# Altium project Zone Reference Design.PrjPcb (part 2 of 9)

## Sheet Input Supply.SchDoc
size 431 x 279 mm; Date: Not shown in title block; ApprovedBy: Not shown in title block; CheckedBy: Not shown in title block; Author: Not shown in title block; CompanyName: Not shown in title block; Engineer: Not shown in title block; Organization: Not shown in title block; Address1: Not shown in title block; Address2: Not shown in title block; Address3: Not shown in title block; Address4: Not shown in title block; DocumentNumber: 1; Revision: Use project parameter SCH_Rev; SheetNumber: 4; SheetTotal: 30; PageSetup: Record=PageOptions¦CenterHorizontal=True¦CenterVertical=True¦PrintScale=1.00¦XCorrection=1.00¦YCorrection=1.00¦PrintKind=0¦BorderSize=5000000¦LeftOffset=0¦BottomOffset=0¦Orientation=2¦PaperLength=1000¦PaperWidth=1000¦Scale=100¦PaperSource=15¦PrintQuality=600¦MediaType=1¦DitherType=10¦PaperKind=Letter¦PrintScaleMode=1
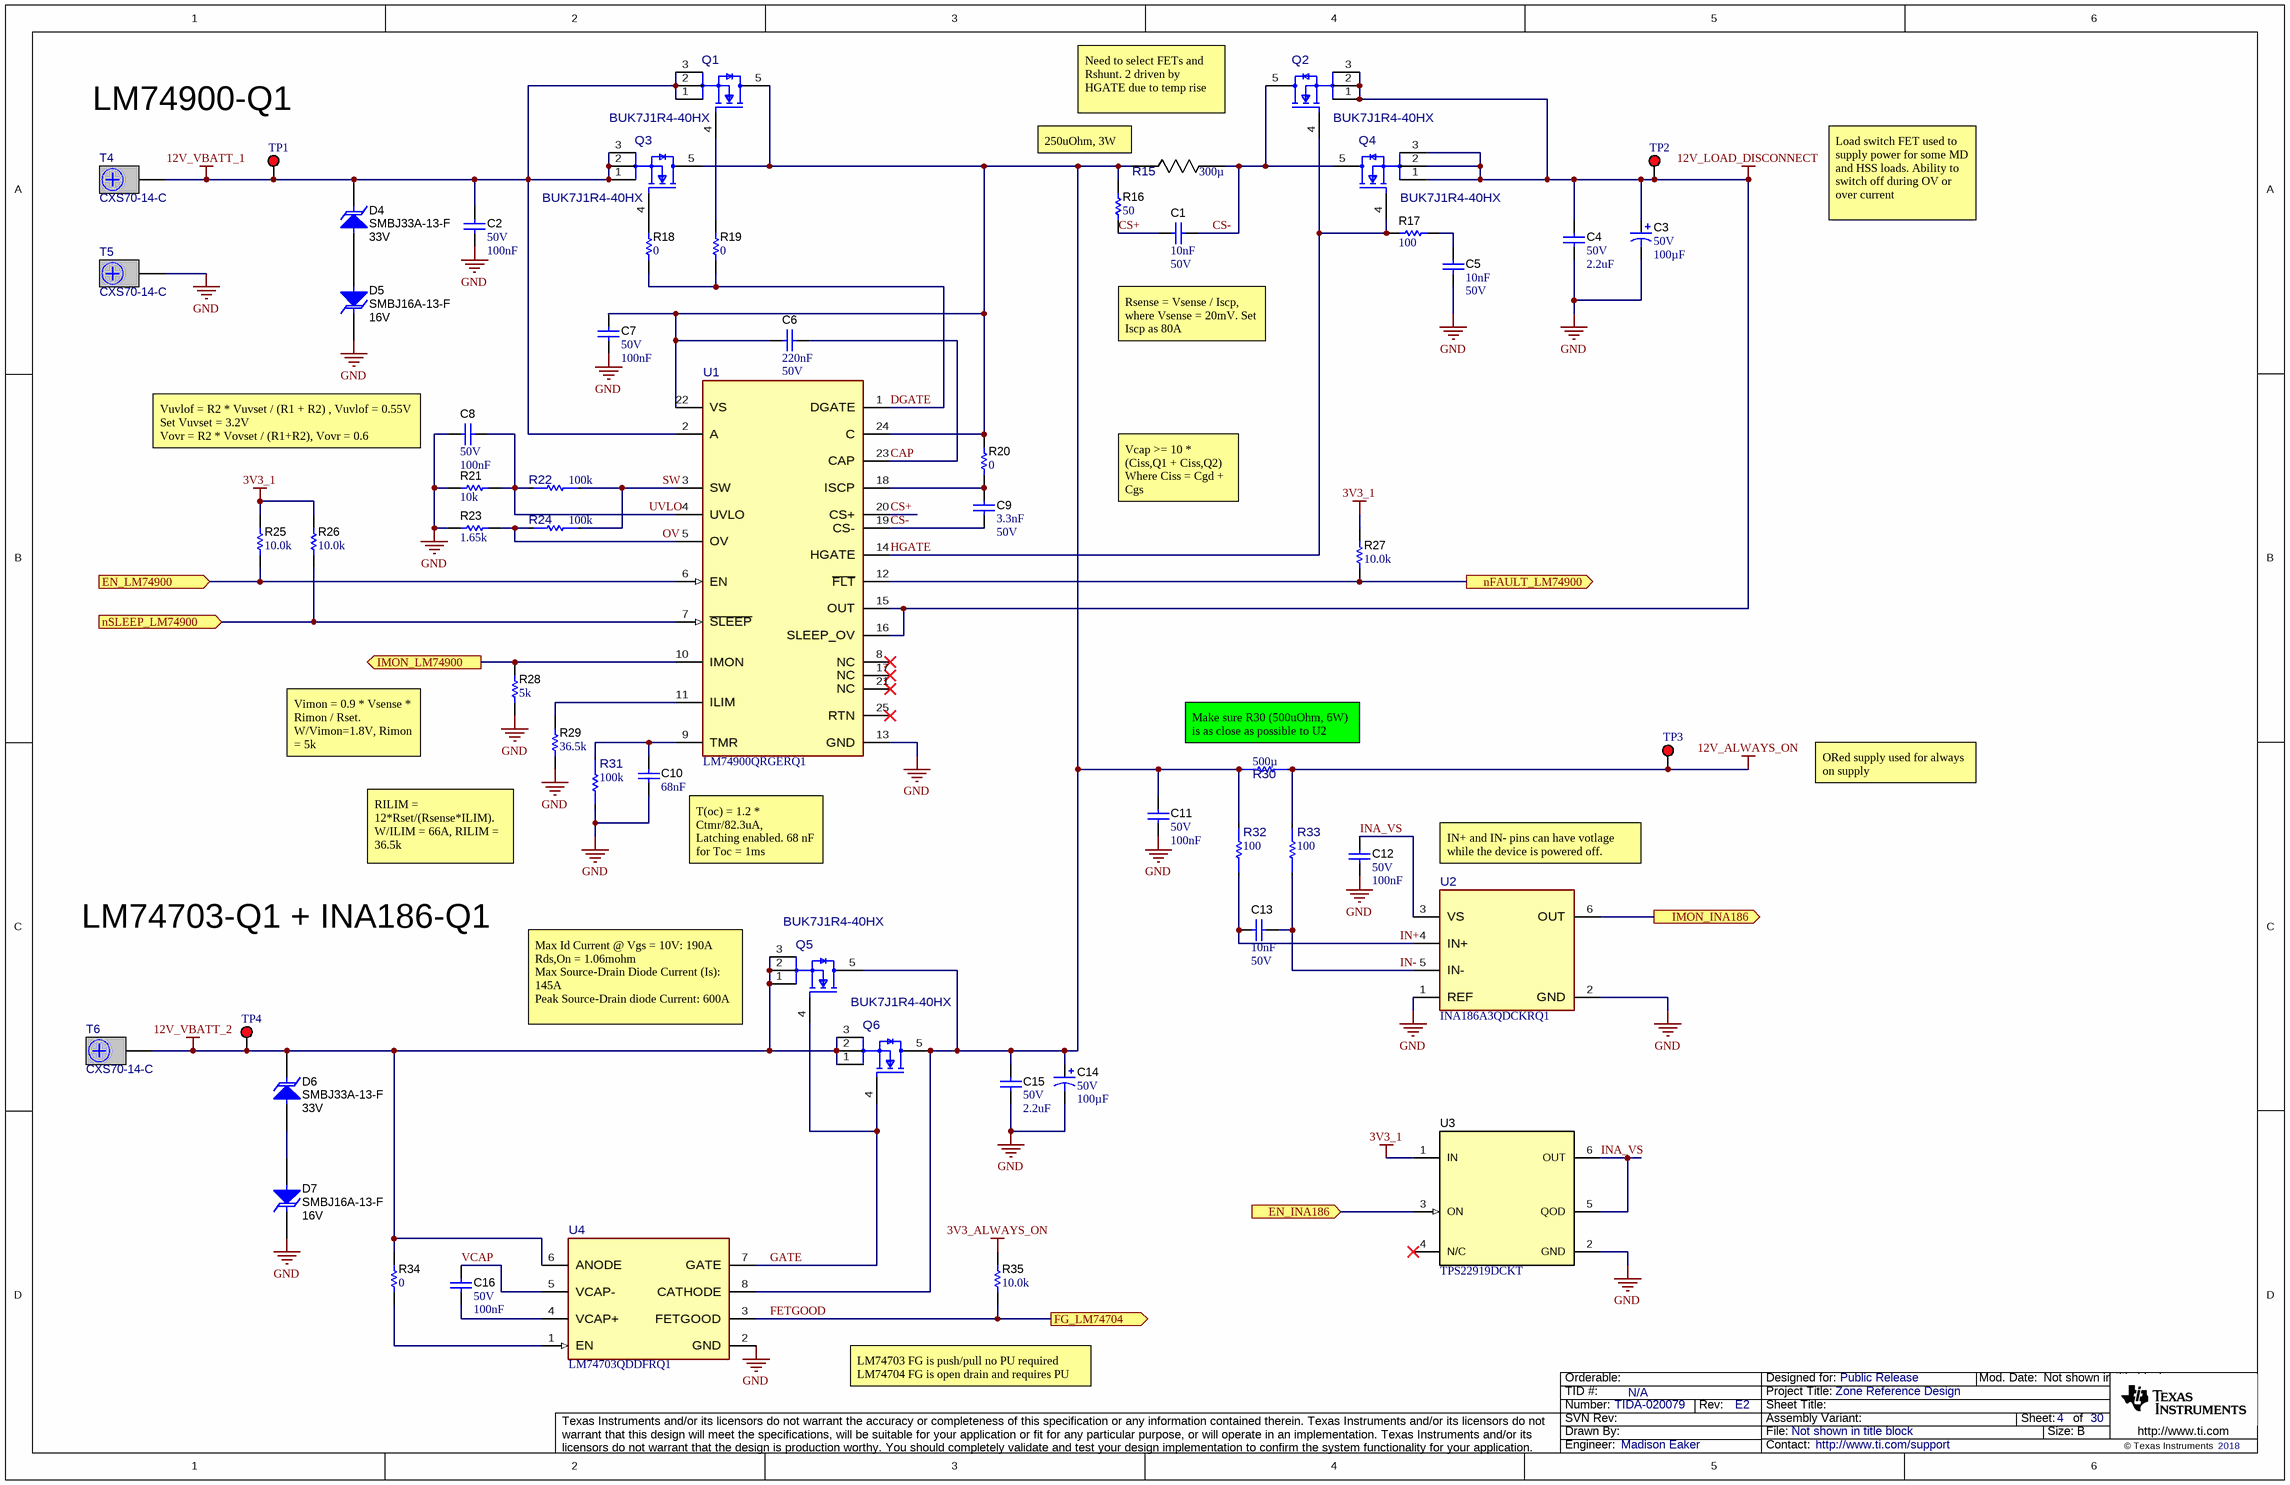
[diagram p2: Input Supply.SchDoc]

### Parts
C1  Cap_F: 10nF  VDC_V: 50V  [0603]  (hidden comment: C0603C103J5RACTU)
C2  VDC_V: 50V  Cap_F: 100nF  [0603L]  (hidden comment: 06035C104K4Z4A)
C3  VDC_V: 50V  ValueDisplayed: 100µF  [Panasonic_SMT_800x1020]  (hidden comment: EEEFP1H101AP)
C4  VDC_V: 50V  ValueDisplayed: 2.2uF  [0603]  (hidden comment: GRM188R61H225KE11D)
C5  Cap_F: 10nF  VDC_V: 50V  [0603]  (hidden comment: C0603C103J5RACTU)
C6  Cap_F: 220nF  VDC_V: 50V  [0603]  (hidden comment: GCM188R71H224KA64D)
C7  VDC_V: 50V  Cap_F: 100nF  [0603L]  (hidden comment: 06035C104K4Z4A)
C8  VDC_V: 50V  Cap_F: 100nF  [0603L]  (hidden comment: 06035C104K4Z4A)
C9  Cap_F: 3.3nF  VDC_V: 50V  [0603]  (hidden comment: C0603C332K5RACTU)
C10  Cap_F: 68nF  [0603]  (hidden comment: 06035C104KAZ2A)
C11  VDC_V: 50V  Cap_F: 100nF  [0603L]  (hidden comment: 06035C104K4Z4A)
C12  VDC_V: 50V  Cap_F: 100nF  [0603L]  (hidden comment: 06035C104K4Z4A)
C13  Cap_F: 10nF  VDC_V: 50V  [0603]  (hidden comment: C0603C103J5RACTU)
C14  VDC_V: 50V  ValueDisplayed: 100µF  [Panasonic_SMT_800x1020]  (hidden comment: EEEFP1H101AP)
C15  VDC_V: 50V  ValueDisplayed: 2.2uF  [0603]  (hidden comment: GRM188R61H225KE11D)
C16  VDC_V: 50V  Cap_F: 100nF  [0603L]  (hidden comment: 06035C104K4Z4A)
D4  SMBJ33A-13-F  value 33V  [SMB]
D5  SMBJ16A-13-F  value 16V  [SMB]
D6  SMBJ33A-13-F  value 33V  [SMB]
D7  SMBJ16A-13-F  value 16V  [SMB]
Q1  BUK7J1R4-40HX  [FP-BUK7J1R4-40HX_LFPAK56E-MFG]
Q2  BUK7J1R4-40HX  [FP-BUK7J1R4-40HX_LFPAK56E-MFG]
Q3  BUK7J1R4-40HX  [FP-BUK7J1R4-40HX_LFPAK56E-MFG]
Q4  BUK7J1R4-40HX  [FP-BUK7J1R4-40HX_LFPAK56E-MFG]
Q5  BUK7J1R4-40HX  [FP-BUK7J1R4-40HX_LFPAK56E-MFG]
Q6  BUK7J1R4-40HX  [FP-BUK7J1R4-40HX_LFPAK56E-MFG]
R15  Res_ohm: 300µ  [FP-PU2512FKGP60U3L_2512 (6432 Metric)-MFG]  (hidden comment: PU2512FKGP60U3L)
R16  ValueDisplayed: 50  [0603]  (hidden comment: CRCW060350R0FKEA)
R17  ValueDisplayed: 100  [0603]  (hidden comment: ERJ-3GEY0R00V)
R18  ValueDisplayed: 0  [0603]  (hidden comment: ERJ-3GEY0R00V)
R19  ValueDisplayed: 0  [0603]  (hidden comment: ERJ-3GEY0R00V)
R20  ValueDisplayed: 0  [0603]  (hidden comment: CRCW060350R0FKEA)
R21  ValueDisplayed: 10k  [0603]  (hidden comment: RT0603BRD0720K8L)
R22  value 100k  [FP-ERJ-PB3B1003V_0603-IPC_A]  (hidden comment: ERJ-PB3B1003V)
R23  ValueDisplayed: 1.65k  [0603]  (hidden comment: RT0603BRD071K62L)
R24  value 100k  [FP-ERJ-PB3B1003V_0603-IPC_A]  (hidden comment: ERJ-PB3B1003V)
R25  ValueDisplayed: 10.0k  [0603]  (hidden comment: ERJ-3EKF1002V)
R26  ValueDisplayed: 10.0k  [0603]  (hidden comment: ERJ-3EKF1002V)
R27  ValueDisplayed: 10.0k  [0603]  (hidden comment: ERJ-3EKF1002V)
R28  ValueDisplayed: 5k  [0603]  (hidden comment: RC0603FR-0730KL)
R29  ValueDisplayed: 36.5k  [0603]  (hidden comment: RC0603FR-0736K5L)
R30  value 500µ  [FP-CSS2H-2512R-L500F_2512-MFG]  (hidden comment: CSS2H-2512R-L500F)
R31  value 100k  [FP-ERJ-PB3B1003V_0603-IPC_A]  (hidden comment: ERJ-PB3B1003V)
R32  value 100  [FP-SG73S1JTTD101J_0603-MFG]  (hidden comment: SG73S1JTTD101J)
R33  value 100  [FP-SG73S1JTTD101J_0603-MFG]  (hidden comment: SG73S1JTTD101J)
R34  ValueDisplayed: 0  [0603]  (hidden comment: ERJ-3GEY0R00V)
R35  ValueDisplayed: 10.0k  [0603]  (hidden comment: ERJ-3EKF1002V)
T4  CXS70-14-C  [Panduit_CXS70-14-C]
T5  CXS70-14-C  [Panduit_CXS70-14-C]
T6  CXS70-14-C  [Panduit_CXS70-14-C]
TP1  5010  [Keystone5010]  (value not drawn)
TP2  5010  [Keystone5010]  (value not drawn)
TP3  5010  [Keystone5010]  (value not drawn)
TP4  5010  [Keystone5010]  (value not drawn)
U1  LM74900QRGERQ1  [RGE0024T-MFG]
U2  INA186A3QDCKRQ1  [DCK0006A-MFG]
U3  TPS22919DCKT  [DCK0006A_N]
U4  LM74703QDDFRQ1  [DDF0008A-MFG]

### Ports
EN_INA186 (in), EN_LM74900 (in), FG_LM74704 (out), IMON_INA186 (out), IMON_LM74900 (out), nFAULT_LM74900 (out), nSLEEP_LM74900 (in)

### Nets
3V3_1: R25.2 R26.2 R27.2 U3.1(IN)
3V3_ALWAYS_ON: R35.2
12V_ALWAYS_ON: R30.2 R33.2 TP3.1
12V_LOAD_DISCONNECT: C3.1(+) C4.1 Q2.1(S) Q2.2(S) Q2.3(S) Q4.1(S) Q4.2(S) Q4.3(S) TP2.1 U1.15(OUT) U1.16(SLEEP_OV)  [project net VS]
12V_VBATT_1: C2.1 D4.1(K) Q1.1(S) Q1.2(S) Q1.3(S) Q3.1(S) Q3.2(S) Q3.3(S) T4.1 TP1.1 U1.2(A)
12V_VBATT_2: D6.1(K) Q5.1(S) Q5.2(S) Q5.3(S) Q6.1(S) Q6.2(S) Q6.3(S) R34.2 T6.1 TP4.1 U4.6(ANODE)
GND: C2.2 C3.2(-) C4.2 C5.1 C7.2 C8.1 C10.2 C11.2 C12.2 C14.2(-) C15.2 D5.1(K) D7.1(K) R21.1 R23.1 R28.2 R29.1 R31.2 T5.1 U1.13(GND) U2.1(REF) U2.2(GND) U3.2(GND) U4.2(GND)
ADC0_AIN0: R28.1 U1.10(IMON) ; port IMON_LM74900
ADC0_AIN1: U2.6(OUT) ; port IMON_INA186
CAP: C6.1 U1.23(CAP)  [project net CAP_4]
CS+: C1.2 R16.1 U1.20(CS+)  [project net CS+_4]
CS-: C1.1 C9.2 Q2.5(D) Q4.5(D) R15.2 U1.19(CS-)  [project net CS-_4]
DGATE: R18.1 R19.1 U1.1(DGATE)  [project net DGATE_4]
EN_INA186: R25.1 U1.6(EN) U3.3(ON) ; port EN_INA186, port EN_LM74900
EPWM5_A: R27.1 U1.12(~{FLT}) ; port nFAULT_LM74900
EQEP0_A: R26.1 U1.7(~{SLEEP}) ; port nSLEEP_LM74900
FETGOOD: R35.1 U4.3(FETGOOD) ; port FG_LM74704
GATE: Q5.4(G) Q6.4(G) U4.7(GATE)  [project net GATE_4]
HGATE: Q2.4(G) Q4.4(G) R17.1 U1.14(HGATE)  [project net HGATE_4]
IN+: C13.2 R32.1 U2.4(IN+)  [project net IN+_4]
IN-: C13.1 R33.1 U2.5(IN-)  [project net IN-_4]
INA_VS: C12.1 U2.3(VS) U3.5(QOD) U3.6(OUT)  [project net INA_VS_4]
OV: R23.2 R24.2 U1.5(OV)  [project net OV_4]
SW: R22.1 R24.1 U1.3(SW)  [project net SW_4]
UVLO: C8.2 R21.2 R22.2 U1.4(UVLO)  [project net UVLO_4]
VCAP: C16.1 U4.5(VCAP-)  [project net VCAP_4]
NetC5_2: C5.2 R17.2
NetC6_2: C6.2 C7.1 C11.1 C14.1(+) C15.1 Q1.5(D) Q3.5(D) Q5.5(D) Q6.5(D) R15.1 R16.2 R20.2 R30.1 R32.2 U1.22(VS) U1.24(C) U4.8(CATHODE)
NetC9_1: C9.1 R20.1 U1.18(ISCP)
NetC10_1: C10.1 R31.1 U1.9(TMR)
NetC16_2: C16.2 U4.4(VCAP+)
NetD4_2: D4.2(A) D5.2(A)
NetD6_2: D6.2(A) D7.2(A)
NetQ1_4: Q1.4(G) R19.2
NetQ3_4: Q3.4(G) R18.2
NetR29_2: R29.2 U1.11(ILIM)
NetR34_1: R34.1 U4.1(EN)

Not connected (* = marked no-connect by the designer): U1 8(NC)* 17(NC)* 21(NC)* 25(RTN)*; U3 4(N/C)*

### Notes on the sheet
- LM74900-Q1
- 250uOhm, 3W
- Need to select FETs and Rshunt. 2 driven by HGATE due to temp rise
- Load switch FET used to supply power for some MD and HSS loads. Ability to switch off during OV or over current
- Rsense = Vsense / Iscp, where Vsense = 20mV. Set Iscp as 80A
- Vuvlof = R2 * Vuvset / (R1 + R2) , Vuvlof = 0.55V
  Set Vuvset = 3.2V
  Vovr = R2 * Vovset / (R1+R2), Vovr = 0.6
- Vcap >= 10 * (Ciss,Q1 + Ciss,Q2)
  Where Ciss = Cgd + Cgs
- Vimon = 0.9 * Vsense * Rimon / Rset. W/Vimon=1.8V, Rimon = 5k
- (near R30) Make sure R30 (500uOhm, 6W) is as close as possible to U2
- ORed supply used for always on supply
- RILIM = 12*Rset/(Rsense*ILIM). W/ILIM = 66A, RILIM = 36.5k
- T(oc) = 1.2 * Ctmr/82.3uA,
  Latching enabled. 68 nF for Toc = 1ms
- IN+ and IN- pins can have votlage while the device is powered off.
- LM74703-Q1 + INA186-Q1
- Max Id Current @ Vgs = 10V: 190A
  Rds,On = 1.06mohm
  Max Source-Drain Diode Current (Is): 145A
  Peak Source-Drain diode Current: 600A
- LM74703 FG is push/pull no PU required
  LM74704 FG is open drain and requires PU

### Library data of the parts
C1 C5 C13 = CMP-0006850-4: CAP, CERM, 0.01 uF, 50 V, +/- 5%, X7R, 0603; Manufacturer: Kemet; TaMin_C: -55°C; Polarized: N; SizeAreaWB_mm2: 4.68; Value1: Unknown; U/M: EA; Value: 0.01uF; TaMax_C: 125°C; SizeZ_mm: 1; SizeX_mm: 1.6; SizeY_mm: 0.8; SizeArea_mm2: 1.28; AEC Category: Q200
C2 C7 C8 C11 C12 C16 = CMP-0084736-1: CAP, CERM, 0.1 µF, 50 V,+/- 10%, X7R, AEC-Q200 Grade 0, 0603; Manufacturer: AVX; SizeX_mm: 1.6; AEC Qualified: Y; Value: 0.1uF; TaMin_C: -55°C; TaMax_C: 125°C; SizeY_mm: 0.8; SizeAreaWB_mm2: 4.68; AEC Grade: 0; SizeArea_mm2: 1.28; SizeZ_mm: 1; ValueDisplayed: 0.1µF; U/M: EA; Cap_Case: 0603; Polarized: N; AEC Category: Q200
C3 C14 = CMP-0077295-1: CAP, AL, 100 µF, 50 V, +/- 20%, 0.18 ohm, AEC-Q200 Grade 2, SMD; Manufacturer: Panasonic; IRMS_A: 670mA; SizeAreaWB_mm2: 106.09; SizeArea_mm2: 68.89; AEC Qualified: Y; AEC Category: Q200; Value: 100uF; TaMax_C: 105°C; SizeZ_mm: 10.5; AEC Grade: 2; TaMin_C: -55°C; SizeY_mm: 8.3; U/M: EA; CompType: Capacitor; ESR_ohm: 0.18; Cap_Case: 8x10.2mm
C4 C15 = CMP-0007353-5: CAP, CERM, 2.2 uF, 50 V, +/- 10%, X5R, 0603; Manufacturer: MuRata; TaMin_C: -55°C; Polarized: N; SizeAreaWB_mm2: 4.68; Value1: Unknown; U/M: EA; Value: 2.2uF; TaMax_C: 85°C; SizeZ_mm: 1; SizeX_mm: 1.6; SizeY_mm: 0.8; SizeArea_mm2: 1.28; Cap_F: 2.2µF; AEC Category: Q200
C6 = CMP-0007145-4: CAP, CERM, 0.22 uF, 50 V, +/- 10%, X7R, AEC-Q200 Grade 1, 0603; Manufacturer: MuRata; TaMin_C: -55°C; Polarized: N; SizeAreaWB_mm2: 4.68; Value1: Unknown; U/M: EA; Value: 0.22uF; TaMax_C: 125°C; SizeZ_mm: 1; SizeX_mm: 1.6; SizeY_mm: 0.8; SizeArea_mm2: 1.28; AEC Qualified: Y; AEC Category: Q200
C9 = CMP-0006922-4: CAP, CERM, 3300 pF, 50 V, +/- 10%, X7R, 0603; Manufacturer: Kemet; TaMin_C: -55°C; Polarized: N; SizeAreaWB_mm2: 4.68; Value1: Unknown; U/M: EA; Value: 3300pF; TaMax_C: 125°C; SizeZ_mm: 1; SizeX_mm: 1.6; SizeY_mm: 0.8; SizeArea_mm2: 1.28; AEC Category: Q200
C10 = CMP-0079095-1: CAP, CERM, 0.1 µF, 50 V,+/- 10%, X7R, AEC-Q200 Grade 1, 0603; Manufacturer: AVX; SizeAreaWB_mm2: 4.68; SizeArea_mm2: 1.28; AEC Qualified: Y; AEC Category: Q200; Value: 0.1uF; TaMax_C: 125°C; SizeZ_mm: 1; Polarized: N; TaMin_C: -55°C; VDC_V: 50V; SizeY_mm: 0.8; U/M: EA; SizeX_mm: 1.6; ValueDisplayed: 0.1µF
D4 D6 = CMP-0005563-4: Diode, TVS, Uni, 33 V, 53.3 Vc, SMB; Manufacturer: Diodes Inc.; Vc: 53.3V; Value1: 600W; Vbr_Max: 42.2V; Vbr_Min: 36.7V; SizeX_mm: 5.6; SizeAreaWB_mm2: 44.156; AEC Category: Q101; SizeY_mm: 3.81; SizeZ_mm: 2.6; Ipp: 11.3A; SizeArea_mm2: 21.336
D5 D7 = CMP-0005547-4: Diode, TVS, Uni, 16 V, 26 Vc, SMB; Manufacturer: Diodes Inc.; SizeArea_mm2: 21.336; SizeY_mm: 3.81; Vbr_Min: 17.8V; Ppk: 600W; AEC Category: Q101; SizeZ_mm: 2.6; Ipp: 23.1A; SizeAreaWB_mm2: 44.156; Vc: 26V; Vbr_Max: 20.5V; SizeX_mm: 5.6
Q1-Q6 = CMP-0098150-1: Trans MOSFET N-CH 40V 190A Automotive 5-Pin(4+Tab) LFPAK T/R; Manufacturer: Nexperia; Drain To Source Breakdown Voltage: 42V; Threshold Vgs Max: 3.6V; Turn On Delay Time: 19ns; ChMode: False; Standoff Height: 0mm; Rdson45_ohm: 1.06m; Power_W: 395W; TJmax_C: +175°C; Pulse Drain Current: 600A; QgTyp_nC: 73nC @ 10V; Vgs_V: 20V; AEC Grade: Grade 0; AEC Qualified: Yes; Turn Off Delay Time: 43ns; VdsMax_V: 1.2V; Input Capacitace At Vds: 5436pF @ 25V; Number Of Channels: 1; SizeZ_mm: 1.25mm; Reverse Recovery Charge: 39nC; Reverse Recovery Time: 37ns; Typ Forward Diode Voltage: 0.8V; Threshold Vgs Min: 2.4V
R15 = CMP-0086899-1: 300 µOhms ±1% 6W Chip Resistor 2512 (6432 Metric) Automotive AEC-Q200, Current Sense, Moisture Resistant Metal Element; Manufacturer: Yageo; SizeZ_mm: 1.08mm; TempCo: 200ppm/°C; AEC Qualified: Yes; Symbol Name: SYM-PU2512FKGP60U3L; AEC Grade: Grade 0
R16 = CMP-0022479-4: RES, 50, 1%, 0.1 W, AEC-Q200 Grade 0, 0603; Manufacturer: Vishay-Dale; Power_W: 100mW; TempCo: 100 ppm/C; Value_Code: 50R0; Value: 50; SizeX_mm: 1.6; SizeY_mm: 0.8; SizeZ_mm: 1; Value2: 0.1W; SizeArea_mm2: 1.28; AEC Qualified: Y; VDC_V: 75V; AEC Category: Q200; AEC Grade: 0
R17-R19 R34 = CMP-0025874-4: RES, 0, 5%, 0.1 W, AEC-Q200 Grade 0, 0603; Manufacturer: Panasonic; Power_W: 100mW; TempCo: 600 ppm/C; Value_Code: 0000; Value: 0; EIA_Code: E24; SizeX_mm: 1.6; SizeY_mm: 0.8; SizeZ_mm: 1; Value2: 0.1W; SizeArea_mm2: 1.28; AEC Qualified: Y; VDC_V: 50V; AEC Category: Q200; SizeAreaWB_mm2: 4.68
R20 = CMP-0022479-4: RES, 50, 1%, 0.1 W, AEC-Q200 Grade 0, 0603; Manufacturer: Vishay-Dale; Power_W: 100mW; TempCo: 100 ppm/C; Value_Code: 50R0; Value: 50; SizeX_mm: 1.6; SizeY_mm: 0.8; SizeZ_mm: 1; Value2: 0.1W; SizeArea_mm2: 1.28; AEC Qualified: Y; VDC_V: 75V; AEC Category: Q200
R21 = CMP-0023930-3: RES, 20.8 k, 0.1%, 0.1 W, 0603; Manufacturer: Yageo America; Power_W: 100mW; TempCo: 25 ppm/C; Value_Code: 20k8; U/M: EA; Value: 20.8k; EIA_Code: E192; SizeX_mm: 1.6; SizeY_mm: 0.8; SizeZ_mm: 1; Value2: 0.1W; SizeArea_mm2: 1.28; VDC_V: 75V; AEC Category: Q200
R22 R24 R31 = CMP-0092407-1: Res Thick Film 0603 100K Ohm 0.1% 0.2W(1/5W) ±50ppm/°C Pad SMD Automotive T/R; Manufacturer: Panasonic; Power_W: 200mW; VDC_V: 150V; AEC Qualified: Yes; SizeZ_mm: 0.55mm; AEC Grade: Grade 0
R23 = CMP-0023900-3: RES, 1.62 k, 0.1%, 0.1 W, 0603; Manufacturer: Yageo America; Power_W: 100mW; TempCo: 25 ppm/C; Value_Code: 1k62; U/M: EA; Value: 1.62k; EIA_Code: E192; SizeX_mm: 1.6; SizeY_mm: 0.8; SizeZ_mm: 1; Value2: 0.1W; SizeArea_mm2: 1.28; VDC_V: 75V; AEC Category: Q200
R25-R27 R35 = CMP-0022684-3: RES, 10.0 k, 1%, 0.1 W, 0603; Manufacturer: Panasonic; Power_W: 100mW; TempCo: 100 ppm/C; Value_Code: 10k0; U/M: EA; Value: 10.0k; EIA_Code: E96; Res_ohm: 10k; SizeX_mm: 1.6; SizeY_mm: 0.8; SizeZ_mm: 1; Value2: 0.1W; SizeArea_mm2: 1.28; VDC_V: 75V; AEC Category: Q200
R28 = CMP-0023020-5: RES, 30.0 k, 1%, 0.1 W, 0603; Manufacturer: Yageo; Power_W: 100mW; TempCo: 100 ppm/C; Value_Code: 30k0; Value: 30.0k; Res_ohm: 30k; SizeX_mm: 1.6; SizeY_mm: 0.8; SizeZ_mm: 1; Value2: 0.1W; SizeArea_mm2: 1.28; AEC Qualified: N; VDC_V: 75V; AEC Category: Q200; SizeAreaWB_mm2: 4.68
R29 = CMP-0023056-5: RES, 36.5 k, 1%, 0.1 W, 0603; Manufacturer: Yageo; Power_W: 100mW; TempCo: 100 ppm/C; Value_Code: 36k5; Value: 36.5k; EIA_Code: E96; SizeX_mm: 1.6; SizeY_mm: 0.8; SizeZ_mm: 1; Value2: 0.1W; SizeArea_mm2: 1.28; AEC Qualified: N; VDC_V: 75V; AEC Category: Q200; SizeAreaWB_mm2: 4.68
R30 = CMP-0095938-1: 500 µOhms ±1% 6W Chip Resistor 2512 (6432 Metric) Automotive AEC-Q200, Current Sense Metal Element; Manufacturer: Bourns; AEC Qualified: Yes; Standoff Height: 0.15mm; SizeZ_mm: 1.23mm; TempCo: 100ppm/°C; AEC Grade: Grade 0
R32 R33 = CMP-0095262-1: 100 Ohms ±5% 0.2W, 1/5W Chip Resistor 0603 (1608 Metric) Automotive AEC-Q200, Moisture Resistant, Pulse Withstanding Thick Film; Manufacturer: KOA Speer; AEC Qualified: Yes; AEC Grade: Grade 0; VDC_V: 150V; TaMax_C: +70°C; TempCo: 100ppm/°C; Power_W: 200mW; SizeZ_mm: 0.55mm
T4-T6 = CMP-0075010-2: Terminal 70A Lug; Manufacturer: Panduit; CompType: Screw Terminal; CT: False; Green_Lifecycle: Not Set; Green_REACh: Incomplete
TP1-TP4 = CMP-0055147-2: Test Point, Multipurpose, Red, TH; Manufacturer: Keystone Electronics; CT: TRUE; ContactFinish: Silver; Green_Lifecycle: Active; CNHeader: FALSE; Green_REACh: Passed
U1 = CMP-0122616-1: Automotive ideal diode with circuit breaker, under- and overvoltage protection with fault output 24-VQFN -40 to 125; Manufacturer: Texas Instruments; SizeZ_mm: 1mm; AEC Qualified: Yes; AEC Grade: Grade 1; Max Supply Voltage: 65V; Min Supply Voltage: 3V; Nominal Supply Current: 630-635uA; Number Of Outputs: 1; Standoff Height: 0mm; TaMax_C: +125°C; TaMin_C: -40°C; TJmax_C: +150°C
U2 = CMP-0121214-1: SP Amp Current Sense Amp Single R-R O/P 5.5V Automotive AEC-Q100 6-Pin SC-70 T/R; Manufacturer: Texas Instruments; SizeZ_mm: 1.1mm; AEC Qualified: Yes; AEC Grade: Grade 1; Bandwidth: 35kHz; Input Bias Current: 0.0005uA; Input Offset Voltage: -0.003mV; Min Supply Voltage: 1.7V; Nominal Supply Current: 48uA; Number Of Channels: 1; Response Time: 30us; Standoff Height: 0mm; TaMax_C: +125°C; TaMin_C: -40°C; TJmax_C: +150°C; Voltage Gain: 0.1V/mV
U3 = CMP-0081107-1: 5.5-V, 1.5-A, 100-mohm Load Switch with Output Discharge, DCK0006A (SOT-SC70-6); Alternate PartNumber: TPS22919DCKR; Alternate Manufacturer: Texas Instruments; SizeAreaWB_mm2: 9.3; SizeZ_mm: 1.1; SizeX_mm: 2.1; SizeY_mm: 2; SizeArea_mm2: 4.2; CompType: IC; AEC Qualified: N; AEC Category: Q200
U4 = CMP-0122213-1: Automotive Ideal Diode Controller With External FET Health Indication; Manufacturer: Texas Instruments; SizeZ_mm: 1.1mm; AEC Qualified: Yes; AEC Grade: Grade 1; Max Supply Voltage: 65V; Min Supply Voltage: 3.2V; Nominal Supply Current: 80uA; Number Of Outputs: 1; Standoff Height: 0mm; TaMax_C: +125°C; TaMin_C: -40°C; TJmax_C: +150°C

## Sheet PMIC.SchDoc
size 431 x 279 mm; Date: Not shown in title block; ApprovedBy: Not shown in title block; CheckedBy: Not shown in title block; Author: Not shown in title block; CompanyName: Not shown in title block; Engineer: Not shown in title block; Organization: Not shown in title block; Address1: Not shown in title block; Address2: Not shown in title block; Address3: Not shown in title block; Address4: Not shown in title block; DocumentNumber: 1; Revision: Use project parameter SCH_Rev; SheetNumber: 3; SheetTotal: 30; PageSetup: Record=PageOptions¦CenterHorizontal=True¦CenterVertical=True¦PrintScale=1.00¦XCorrection=1.00¦YCorrection=1.00¦PrintKind=0¦BorderSize=5000000¦LeftOffset=0¦BottomOffset=0¦Orientation=2¦PaperLength=1000¦PaperWidth=1000¦Scale=100¦PaperSource=15¦PrintQuality=600¦MediaType=1¦DitherType=10¦PaperKind=Letter¦PrintScaleMode=1
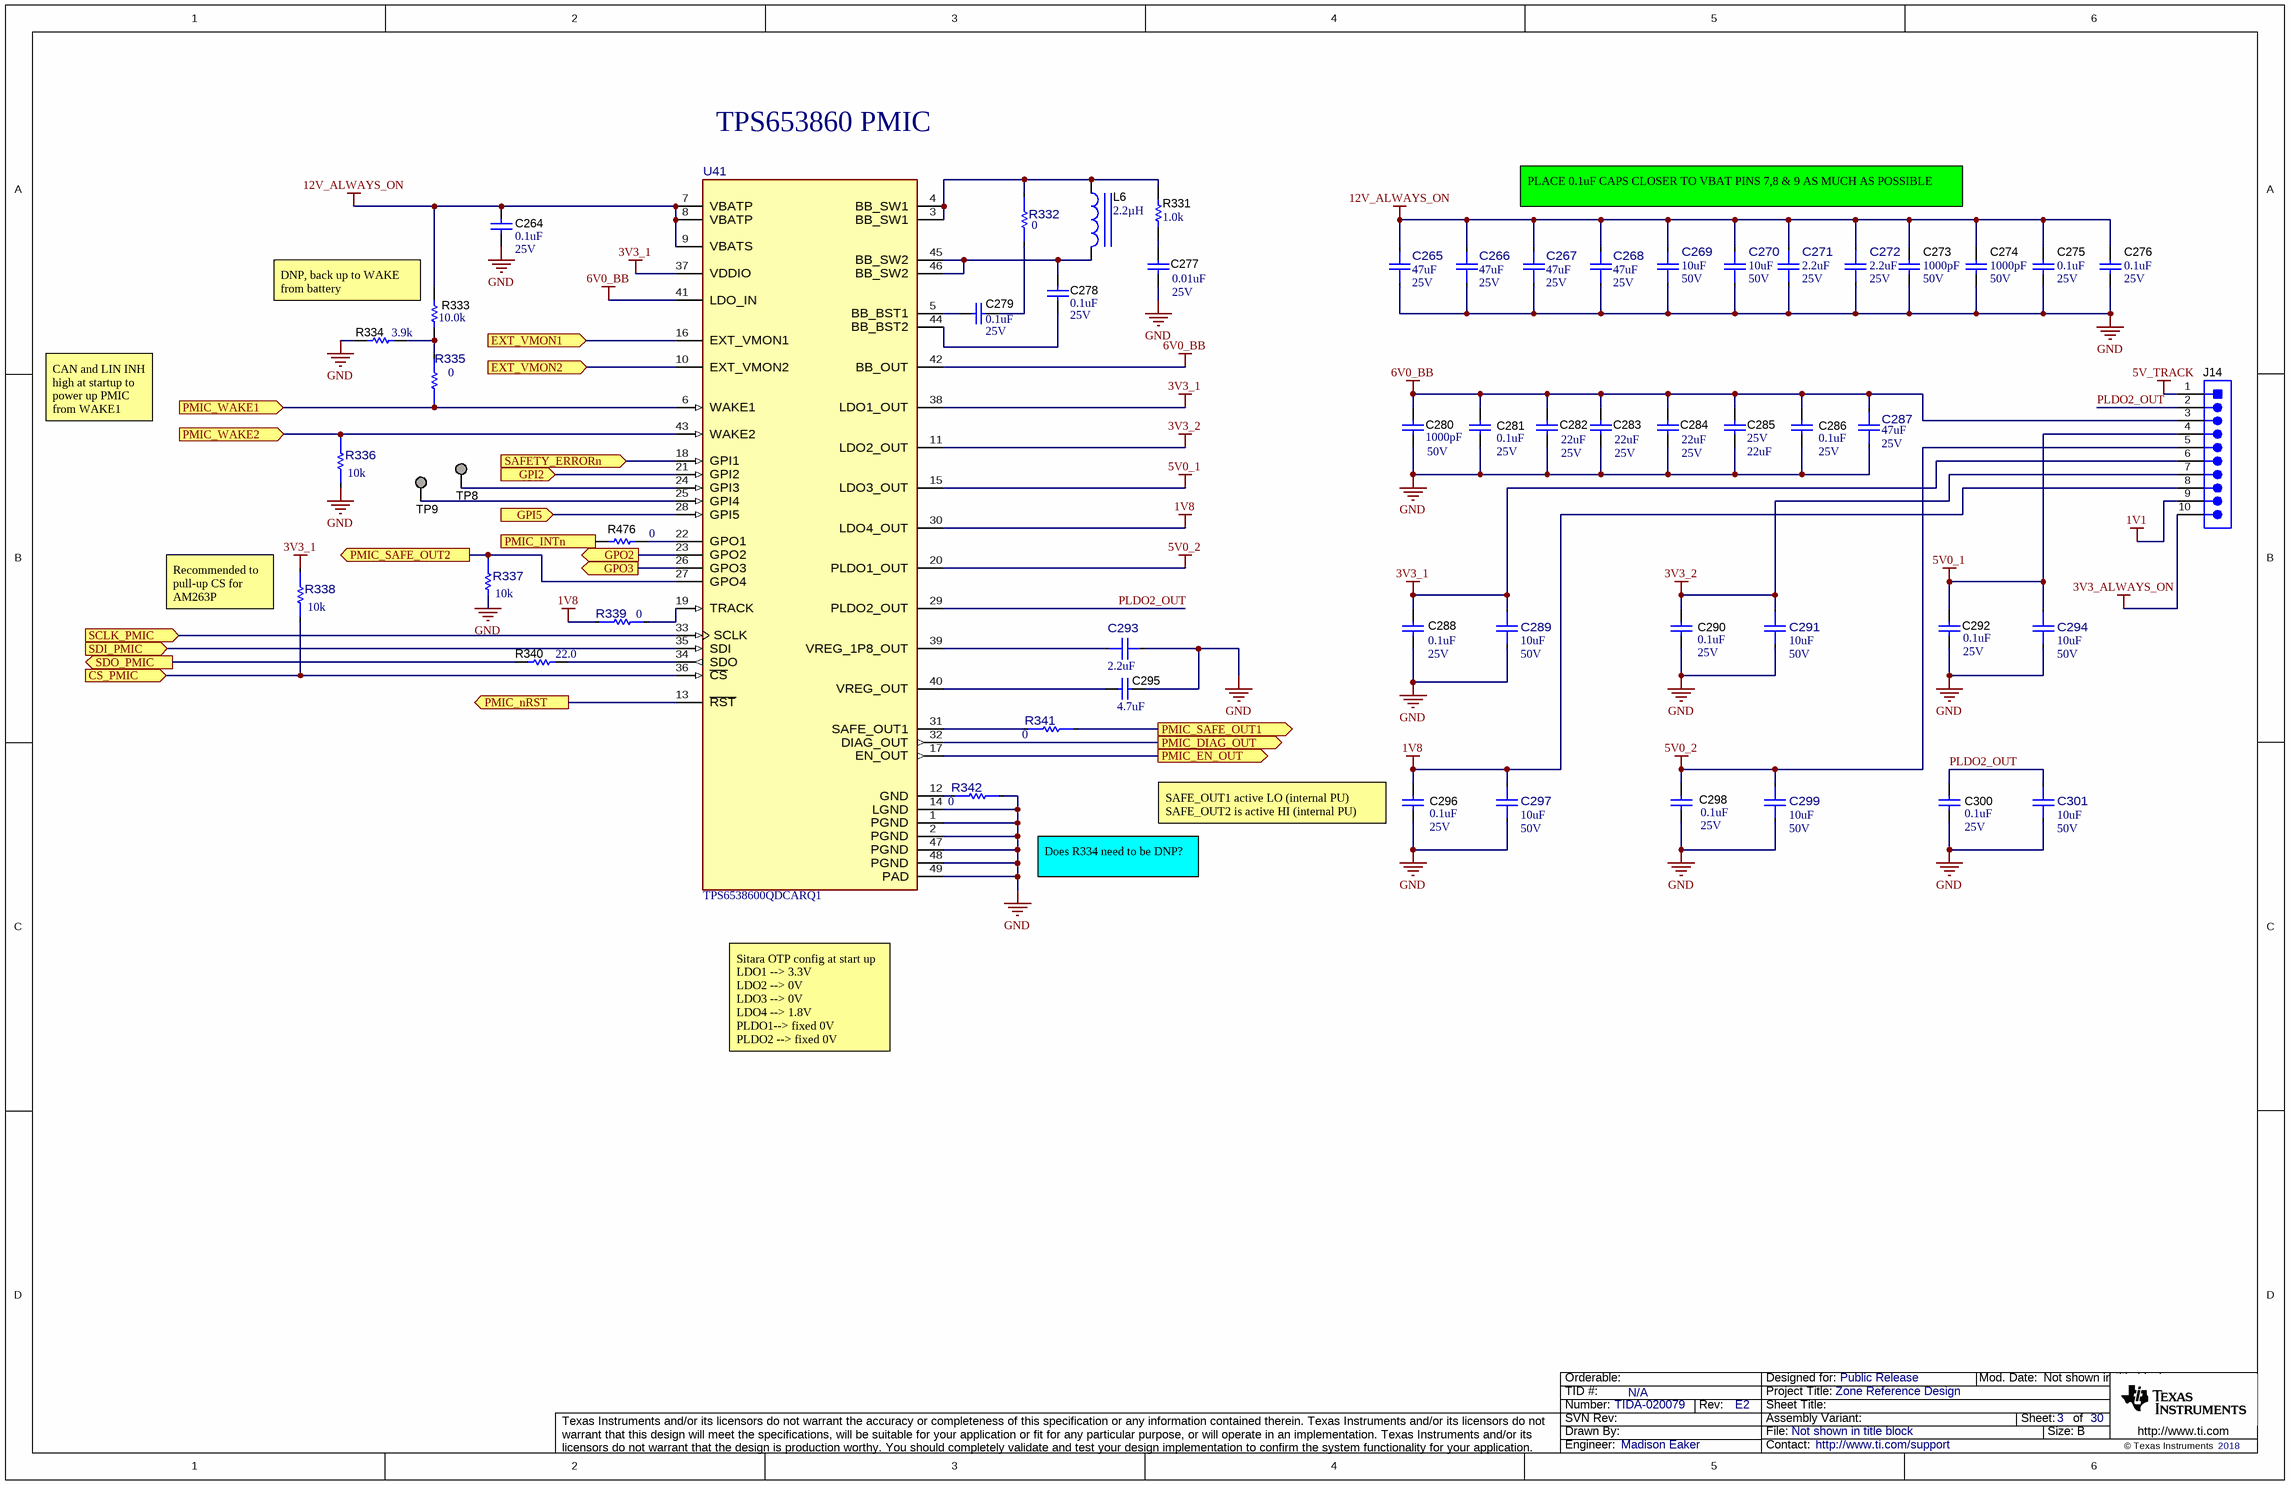
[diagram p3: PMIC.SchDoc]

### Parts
C264  VDC_V: 25V  ValueDisplayed: 0.1uF  [0402]  (hidden comment: GRM155R71E104KE14D)
C265  ValueDisplayed: 47uF  VDC_V: 25V  [FP-GMC31X5R476M25NT_1206-MFG]  (hidden comment: GMC31X5R476M25NT)
C266  ValueDisplayed: 47uF  VDC_V: 25V  [FP-GMC31X5R476M25NT_1206-MFG]  (hidden comment: GMC31X5R476M25NT)
C267  ValueDisplayed: 47uF  VDC_V: 25V  [FP-GMC31X5R476M25NT_1206-MFG]  (hidden comment: GMC31X5R476M25NT)
C268  ValueDisplayed: 47uF  VDC_V: 25V  [FP-GMC31X5R476M25NT_1206-MFG]  (hidden comment: GMC31X5R476M25NT)
C269  ValueDisplayed: 10uF  VDC_V: 50V  [FP-GRM21BR61H106KE43L_0805-MFG]  (hidden comment: GRM21BR61H106KE43L)
C270  ValueDisplayed: 10uF  VDC_V: 50V  [FP-GRM21BR61H106KE43L_0805-MFG]  (hidden comment: GRM21BR61H106KE43L)
C271  ValueDisplayed: 2.2uF  VDC_V: 25V  [FP-GRM155R61E225KE11D_0402 (1005 metric)-MFG]  (hidden comment: GRM155R61E225KE11D)
C272  ValueDisplayed: 2.2uF  VDC_V: 25V  [FP-GRM155R61E225KE11D_0402 (1005 metric)-MFG]  (hidden comment: GRM155R61E225KE11D)
C273  Value2: 50V  ValueDisplayed: 1000pF  [0402]  (hidden comment: GRM1555C1H102JA01D)
C274  Value2: 50V  ValueDisplayed: 1000pF  [0402]  (hidden comment: GRM1555C1H102JA01D)
C275  Value2: 25V  ValueDisplayed: 0.1uF  [0402]  (hidden comment: GRM155R71E104KE14D)
C276  Value2: 25V  ValueDisplayed: 0.1uF  [0402]  (hidden comment: GRM155R71E104KE14D)
C277  Value2: 25V  ValueDisplayed: 0.01uF  [0402]  (hidden comment: GCM155R71E103KA37D)
C278  VDC_V: 25V  ValueDisplayed: 0.1uF  [0402]  (hidden comment: GRM155R71E104KE14D)
C279  VDC_V: 25V  ValueDisplayed: 0.1uF  [0402]  (hidden comment: GRM155R71E104KE14D)
C280  VDC_V: 50V  ValueDisplayed: 1000pF  [0402]  (hidden comment: GRM1555C1H102JA01D)
C281  VDC_V: 25V  ValueDisplayed: 0.1uF  [0402]  (hidden comment: GRM155R71E104KE14D)
C282  VDC_V: 25V  ValueDisplayed: 22uF  [0805_HV]  (hidden comment: GRM21BR61E226ME44L)
C283  VDC_V: 25V  ValueDisplayed: 22uF  [0805_HV]  (hidden comment: GRM21BR61E226ME44L)
C284  VDC_V: 25V  ValueDisplayed: 22uF  [0805_HV]  (hidden comment: GRM21BR61E226ME44L)
C285  VDC_V: 25V  ValueDisplayed: 22uF  [0805_HV]  (hidden comment: GRM21BR61E226ME44L)
C286  VDC_V: 25V  ValueDisplayed: 0.1uF  [0402]  (hidden comment: GRM155R71E104KE14D)
C287  ValueDisplayed: 47uF  VDC_V: 25V  [FP-GMC31X5R476M25NT_1206-MFG]  (hidden comment: GMC31X5R476M25NT)
C288  VDC_V: 25V  ValueDisplayed: 0.1uF  [0402]  (hidden comment: GRM155R71E104KE14D)
C289  ValueDisplayed: 10uF  VDC_V: 50V  [FP-GRM21BR61H106KE43L_0805-MFG]  (hidden comment: GRM21BR61H106KE43L)
C290  VDC_V: 25V  ValueDisplayed: 0.1uF  [0402]  (hidden comment: GRM155R71E104KE14D)
C291  ValueDisplayed: 10uF  VDC_V: 50V  [FP-GRM21BR61H106KE43L_0805-MFG]  (hidden comment: GRM21BR61H106KE43L)
C292  VDC_V: 25V  ValueDisplayed: 0.1uF  [0402]  (hidden comment: GRM155R71E104KE14D)
C293  ValueDisplayed: 2.2uF  [FP-GRM155R61E225KE11D_0402 (1005 metric)-MFG]  (hidden comment: GRM155R61E225KE11D)
C294  ValueDisplayed: 10uF  VDC_V: 50V  [FP-GRM21BR61H106KE43L_0805-MFG]  (hidden comment: GRM21BR61H106KE43L)
C295  ValueDisplayed: 4.7uF  [0402]  (hidden comment: GRM155R61A475MEAAD)
C296  VDC_V: 25V  ValueDisplayed: 0.1uF  [0402]  (hidden comment: GRM155R71E104KE14D)
C297  ValueDisplayed: 10uF  VDC_V: 50V  [FP-GRM21BR61H106KE43L_0805-MFG]  (hidden comment: GRM21BR61H106KE43L)
C298  VDC_V: 25V  ValueDisplayed: 0.1uF  [0402]  (hidden comment: GRM155R71E104KE14D)
C299  ValueDisplayed: 10uF  VDC_V: 50V  [FP-GRM21BR61H106KE43L_0805-MFG]  (hidden comment: GRM21BR61H106KE43L)
C300  VDC_V: 25V  ValueDisplayed: 0.1uF  [0402]  (hidden comment: GRM155R71E104KE14D)
C301  ValueDisplayed: 10uF  VDC_V: 50V  [FP-GRM21BR61H106KE43L_0805-MFG]  (hidden comment: GRM21BR61H106KE43L)
J14  TSW-110-07-G-S  [TSW-110-07-G-S]  (value not drawn)
L6  ValueDisplayed: 2.2µH  [CLF7045NI-D]  (hidden comment: CLF7045NIT-2R2N-D)
R331  ValueDisplayed: 1.0k  [0402]  (hidden comment: ERJ-2GEJ102X)
R332  value 0  [FP-ERJ-2GE0R00X_0402-MFG]  (hidden comment: ERJ-2GE0R00X)
R333  ValueDisplayed: 10.0k  [0402]  (hidden comment: AC0402FR-0710KL)
R334  ValueDisplayed: 3.9k  [0402]  (hidden comment: CRCW04023K90JNED)
R335  value 0  [FP-ERJ-2GE0R00X_0402-MFG]  (hidden comment: ERJ-2GE0R00X)
R336  value 10k  [FP-RC0402JR-0710KL_0402-MFG]  (hidden comment: RC0402JR-0710KL)
R337  value 10k  [FP-RC0402JR-0710KL_0402-MFG]  (hidden comment: RC0402JR-0710KL)
R338  value 10k  [FP-RC0402JR-0710KL_0402-MFG]  (hidden comment: RC0402JR-0710KL)
R339  value 0  [FP-ERJ-2GE0R00X_0402-MFG]  (hidden comment: ERJ-2GE0R00X)
R340  ValueDisplayed: 22.0  [0201]  (hidden comment: RC0201FR-0722RL)
R341  value 0  [FP-ERJ-2GE0R00X_0402-MFG]  (hidden comment: ERJ-2GE0R00X)
R342  value 0  [FP-ERJ-2GE0R00X_0402-MFG]  (hidden comment: ERJ-2GE0R00X)
R476  ValueDisplayed: 0  [0603]  (hidden comment: CRCW06030000Z0EA)
TP8  TESTPOINT  [TP_25MIL-SMT]  (value not drawn)  (no BOM)
TP9  TESTPOINT  [TP_25MIL-SMT]  (value not drawn)  (no BOM)
U41  TPS6538600QDCARQ1  [DCA0048J-MFG]

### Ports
CS_PMIC (in), EXT_VMON1 (in), EXT_VMON2 (in), GPI2 (in), GPI5 (in), GPO2 (out), GPO3 (out), PMIC_DIAG_OUT (out), PMIC_EN_OUT (out), PMIC_INTn (out), PMIC_nRST (out), PMIC_SAFE_OUT1 (out), PMIC_SAFE_OUT2 (out), PMIC_WAKE1 (in), PMIC_WAKE2 (in), SAFETY_ERRORn (in), SCLK_PMIC (in), SDI_PMIC (in), SDO_PMIC (out)

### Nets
1V1: J14.9
1V8: C296.1 C297.1 J14.8 R339.1 U41.30(LDO4_OUT)
3V3_1: C288.1 C289.1 J14.6 R338.1 U41.37(VDDIO) U41.38(LDO1_OUT)
3V3_2: C290.1 C291.1 J14.7 U41.11(LDO2_OUT)
3V3_ALWAYS_ON: J14.10
5V0_1: C292.1 C294.1 J14.4 U41.15(LDO3_OUT)
5V0_2: C298.1 C299.1 J14.5 U41.20(PLDO1_OUT)
5V_TRACK: J14.1
6V0_BB: C280.1 C281.1 C282.2 C283.2 C284.2 C285.2 C286.1 C287.2 J14.3 U41.41(LDO_IN) U41.42(BB_OUT)
12V_ALWAYS_ON: C264.1 C265.2 C266.2 C267.2 C268.2 C269.2 C270.2 C271.1 C272.1 C273.2 C274.2 C275.1 C276.1 R333.2 U41.7(VBATP) U41.8(VBATP) U41.9(VBATS)
GND: C264.2 C265.1 C266.1 C267.1 C268.1 C269.1 C270.1 C271.2 C272.2 C273.1 C274.1 C275.2 C276.2 C277.2 C280.2 C281.2 C282.1 C283.1 C284.1 C285.1 C286.2 C287.1 C288.2 C289.2 C290.2 C291.2 C292.2 C293.2 C294.2 C295.1 C296.2 C297.2 C298.2 C299.2 C300.2 C301.2 R334.1 R336.2 R337.2 R342.2 U41.1(PGND) U41.2(PGND) U41.14(LGND) U41.47(PGND) U41.48(PGND) U41.49(PAD)
CS_PMIC: R338.2 U41.36(~{CS}) ; port CS_PMIC
EXT_VMON1: U41.16(EXT_VMON1) ; port EXT_VMON1
EXT_VMON2: U41.10(EXT_VMON2) ; port EXT_VMON2
GPI2: U41.21(GPI2) ; port GPI2
GPI5: U41.28(GPI5) ; port GPI5
GPO2: U41.23(GPO2) ; port GPO2
GPO3: U41.26(GPO3) ; port GPO3
INH_TCAN1043A: R335.1 U41.6(WAKE1) ; port PMIC_WAKE1
LHI_HCS: R337.1 U41.27(GPO4) ; port PMIC_SAFE_OUT2
PLDO2_OUT: C300.1 C301.1 J14.2 U41.29(PLDO2_OUT)  [project net PLDO2_OUT_3]
PMIC_DIAG: U41.32(DIAG_OUT) ; port PMIC_DIAG_OUT
PMIC_EN_OUT: U41.17(EN_OUT) ; port PMIC_EN_OUT
PMIC_nINT: R476.2 ; port PMIC_INTn
PMIC_nRST: U41.13(~{RST}) ; port PMIC_nRST
SAFE_OUT1: R341.2 ; port PMIC_SAFE_OUT1
SAFETY_ERRORn: U41.18(GPI1) ; port SAFETY_ERRORn
SCLK_PMIC: U41.33(SCLK) ; port SCLK_PMIC
SDI_PMIC: U41.35(SDI) ; port SDI_PMIC
SDO_PMIC: R340.1 ; port SDO_PMIC
WAKE2: R336.1 U41.43(WAKE2) ; port PMIC_WAKE2
NetC277_1: C277.1 R331.2
NetC278_1: C278.1 L6.2 U41.45(BB_SW2) U41.46(BB_SW2)
NetC278_2: C278.2 U41.44(BB_BST2)
NetC279_1: C279.1 R332.2
NetC279_2: C279.2 U41.5(BB_BST1)
NetC293_1: C293.1 U41.39(VREG_1P8_OUT)
NetC295_2: C295.2 U41.40(VREG_OUT)
NetL6_1: L6.1 R331.1 R332.1 U41.3(BB_SW1) U41.4(BB_SW1)
NetR333_1: R333.1 R334.2 R335.2
NetR339_2: R339.2 U41.19(TRACK)
NetR340_2: R340.2 U41.34(SDO)
NetR341_1: R341.1 U41.31(SAFE_OUT1)
NetR342_1: R342.1 U41.12(GND)
NetR476_1: R476.1 U41.22(GPO1)
NetTP8_1: TP8.1 U41.24(GPI3)
NetTP9_1: TP9.1 U41.25(GPI4)

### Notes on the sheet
- TPS653860 PMIC
- PLACE 0.1uF CAPS CLOSER TO VBAT PINS 7,8 & 9 AS MUCH AS POSSIBLE
- (near R333) DNP, back up to WAKE from battery
- CAN and LIN INH high at startup to power up PMIC from WAKE1
- (near R338) Recommended to pull-up CS for AM263P
- (near C296) SAFE_OUT1 active LO (internal PU)
  SAFE_OUT2 is active HI (internal PU)
- Does R334 need to be DNP?
- Sitara OTP config at start up
  LDO1 --> 3.3V
  LDO2 --> 0V
  LDO3 --> 0V
  LDO4 --> 1.8V
  PLDO1--> fixed 0V
  PLDO2 --> fixed 0V

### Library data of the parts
C264 C275 C276 C278 C279 C281 C286 C288 C290 C292 C296 C298 C300 = CMP-0006659-2: CAP, CERM, 0.1 uF, 25 V, +/- 10%, X7R, 0402; Manufacturer: MuRata; TaMin_C: -55°C; Polarized: N; SizeAreaWB_mm2: 3; Value1: Unknown; U/M: EA; Value: 0.1uF; TaMax_C: 125°C; SizeZ_mm: 0.6; SizeX_mm: 1; SizeY_mm: 0.5; Cap_F: 100nF; AEC Category: Q200
C265-C268 C287 = CMP-0124829-1: 47 µF ±20% 25V Ceramic Capacitor X5R 1206 (3216 Metric); Manufacturer: Cal-Chip Electronics; AEC Qualified: No; Cap_F: 47µF; SizeZ_mm: 1.8mm; TempCo: 15%; Value: 47µF
C269 C270 C289 C291 C294 C297 C299 C301 = CMP-0122097-1: Chip Multilayer Ceramic Capacitors for General Purpose, 0805, 10uF, X5R, 15%, 10%, 50V; Manufacturer: Murata; AEC Qualified: No; Cap_F: 10µF; SizeZ_mm: 1.45mm; Value: 10µF
C271 C272 C293 = CMP-0089929-1: 2.2µF ±10% 25V Ceramic Capacitor X5R 0402 (1005 Metric); Manufacturer: Murata; SizeZ_mm: 0.7mm; AEC Qualified: No; TempCo: 15%
C273 C274 C280 = CMP-0006412-2: CAP, CERM, 1000 pF, 50 V, +/- 5%, C0G/NP0, 0402; Manufacturer: MuRata; TaMin_C: -55°C; Polarized: N; SizeAreaWB_mm2: 3; Value1: Unknown; U/M: EA; Value: 1000pF; TaMax_C: 125°C; SizeZ_mm: 0.6; SizeX_mm: 1; SizeY_mm: 0.5; Cap_F: 1nF; AEC Category: Q200
C277 = CMP-0006352-2: CAP, CERM, 0.01 uF, 25 V, +/- 10%, X7R, 0402; Manufacturer: MuRata; TaMin_C: -55°C; Polarized: N; SizeAreaWB_mm2: 3; Value1: Unknown; U/M: EA; Value: 0.01uF; TaMax_C: 125°C; SizeZ_mm: 0.6; SizeX_mm: 1; SizeY_mm: 0.5; Cap_F: 10nF; AEC Category: Q200
C282-C285 = CMP-0008305-2: CAP, CERM, 22 uF, 25 V, +/- 20%, X5R, 0805; Manufacturer: MuRata; TaMin_C: -55°C; Polarized: N; SizeAreaWB_mm2: 6.75; Value1: Unknown; U/M: EA; Value: 22uF; TaMax_C: 85°C; SizeZ_mm: 1.45; SizeX_mm: 2; SizeY_mm: 1.25; Cap_Case: 0805; SizeArea_mm2: 2.5; Cap_F: 22µF; AEC Category: Q200
C295 = CMP-0006582-2: CAP, CERM, 4.7 uF, 10 V, +/- 20%, X5R, 0402; Manufacturer: MuRata; TaMin_C: -55°C; Polarized: N; SizeAreaWB_mm2: 3; Value1: Unknown; U/M: EA; Value: 4.7uF; TaMax_C: 85°C; SizeZ_mm: 0.6; SizeX_mm: 1; SizeY_mm: 0.5; Value2: 10V; Cap_F: 4.7µF; AEC Category: Q200
J14 = CMP-0075422-1: Header, 100mil, 10x1, Gold, TH; Manufacturer: Samtec; Pitch_mm: 2.54; Cert_VDE: N; Gender: Male; Cert_CSA: Y; Voltage_V: 550V; Green_REACh: Passed; Current_A: 6.3A; CT: False; Green_Lifecycle: Active; Row_Count: 1; CNHeader: True
L6 = CMP-0080400-2: Inductor, Shielded, Ferrite, 2.2 µH, 5.1 A, 0.017 ohm, AEC-Q200 Grade 0, SMD; Manufacturer: TDK; Isat: 6.2A @ 30% inductance drop; Irms: 5.1A @ 40C rise; SizeAreaWB_mm2: 84.6; DCR_ohm: 17m; Value: 2.2uH; Imax_A: 5.1A; SizeZ_mm: 4.8; SizeX_mm: 7.4; SizeY_mm: 7; SizeArea_mm2: 51.8; AEC Qualified: Y; AEC Grade: 0; AEC Category: Q200
R331 = CMP-0078193-1: RES, 1.0 k, 5%, 0.1 W, AEC-Q200 Grade 0, 0402; Manufacturer: Panasonic; Power_W: 100mW; TempCo: 200 ppm/C; Value_Code: 1k00; U/M: EA; Value: 1.0k; EIA_Code: E24; Res_ohm: 1k; SizeX_mm: 1; SizeY_mm: 0.5; SizeZ_mm: 0.6; Value2: 0.1W; AEC Qualified: Y; VDC_V: 50V; AEC Category: Q200; AEC Grade: 0; Green_REACh: Passed; Green_Lifecycle: Active
R332 R339 R341 R342 = CMP-0002710-1: 0 Ohms Jumper Chip Resistor 0402 (1005 Metric) Automotive AEC-Q200 Thick Film; Manufacturer: Panasonic; AEC Grade: Grade 0; AEC Qualified: Yes; SizeZ_mm: 0.4mm; Power: 100mW
R333 = CMP-0077731-1: RES, 10.0 k, 1%, 0.063 W, AEC-Q200 Grade 0, 0402; Manufacturer: Yageo America; Power_W: 63mW; TempCo: 100 ppm/C; Value_Code: 10k0; U/M: EA; Value: 10.0k; EIA_Code: E96; Res_ohm: 10k; SizeX_mm: 1.0; SizeY_mm: 0.5; SizeZ_mm: 0.6; Value2: 0.063W; AEC Qualified: Y; VDC_V: 50V; AEC Grade: 0; AEC Category: Q200
R334 = CMP-0026920-5: RES, 3.9 k, 5%, 0.063 W, AEC-Q200 Grade 0, 0402; Manufacturer: Vishay-Dale; Power_W: 63mW; TempCo: 200 ppm/C; Value_Code: 3k90; Value: 3.9k; EIA_Code: E24; SizeX_mm: 1; SizeY_mm: 0.5; SizeZ_mm: 0.6; Value2: 0.063W; AEC Qualified: Y; VDC_V: 50V; AEC Category: Q200; AEC Grade: 0
R335 = CMP-0002710-1: 0 Ohms Jumper Chip Resistor 0402 (1005 Metric) Automotive AEC-Q200 Thick Film; Manufacturer: Panasonic; SizeZ_mm: 0.4mm; AEC Qualified: Yes; AEC Grade: Grade 0; Power: 100mW
R336-R338 = CMP-0094798-1: Res Thick Film 0402 10K Ohm 5% 0.063W(1/16W) ±100ppm/C Pad SMD T/R; Manufacturer: YAGEO; AEC Qualified: No; Category Cd01000Bfc2916C6: Single Components; SizeZ_mm: 0.4mm; VDC_V: 50V; Category 5C6A91606D4187Ad: Resistors; TempCo: 100ppm/°C; Power_W: 63mW; Category 7542B8484461Ae85: Passive Components
R340 = CMP-0027500-1: RES, 22.0, 1%, 0.05 W, 0201; Manufacturer: Yageo America; Power_W: 50mW; TempCo: 200 ppm/C; Value_Code: 22R0; U/M: EA; Value: 22.0; Res_ohm: 22; SizeX_mm: 0.6; SizeY_mm: 0.3; SizeZ_mm: 0.26; Value2: 0.05W; SizeArea_mm2: 0.18; AEC Qualified: N; VDC_V: 25V; AEC Category: Q200
R476 = CMP-0025697-4: RES, 0, 5%, 0.1 W, AEC-Q200 Grade 0, 0603; Manufacturer: Vishay-Dale; Power_W: 100mW; TempCo: 200 ppm/C; Value_Code: 0000; Value: 0; EIA_Code: E24; SizeX_mm: 1.6; SizeY_mm: 0.8; SizeZ_mm: 1; Value2: 0.1W; SizeArea_mm2: 1.28; CompType: Resistor; AEC Qualified: Y; VDC_V: 75V; AEC Category: Q200
TP8 TP9 = CMP-0078143-3: TEST POINT.  No entry in BOM.
U41 = CMP-0095884-1: Power Management IC For Safety-Relevant Applications HTSSOP48 5 Outputs 4 LDO and 1 Synchronous Buck-Boost Regulator; Manufacturer: Texas Instruments; SizeZ_mm: 1.2mm; AEC Qualified: Yes; Standoff Height: 0.05mm; Max Supply Voltage: 28V; TaMin_C: -40°C; AEC Grade: Grade 1; TJmax_C: +150°C; Min Supply Voltage: 2.3V; Number Of Outputs: 7; TaMax_C: +125°C

## Sheet BUCKs and LDO.SchDoc
size 431 x 279 mm; Date: Not shown in title block; ApprovedBy: Not shown in title block; CheckedBy: Not shown in title block; Author: Not shown in title block; CompanyName: Not shown in title block; Engineer: Not shown in title block; Organization: Not shown in title block; Address1: Not shown in title block; Address2: Not shown in title block; Address3: Not shown in title block; Address4: Not shown in title block; DocumentNumber: 1; Revision: Use project parameter SCH_Rev; SheetNumber: 5; SheetTotal: 30; PageSetup: Record=PageOptions¦CenterHorizontal=True¦CenterVertical=True¦PrintScale=1.00¦XCorrection=1.00¦YCorrection=1.00¦PrintKind=0¦BorderSize=5000000¦LeftOffset=0¦BottomOffset=0¦Orientation=2¦PaperLength=1000¦PaperWidth=1000¦Scale=100¦PaperSource=15¦PrintQuality=600¦MediaType=1¦DitherType=10¦PaperKind=Letter¦PrintScaleMode=1
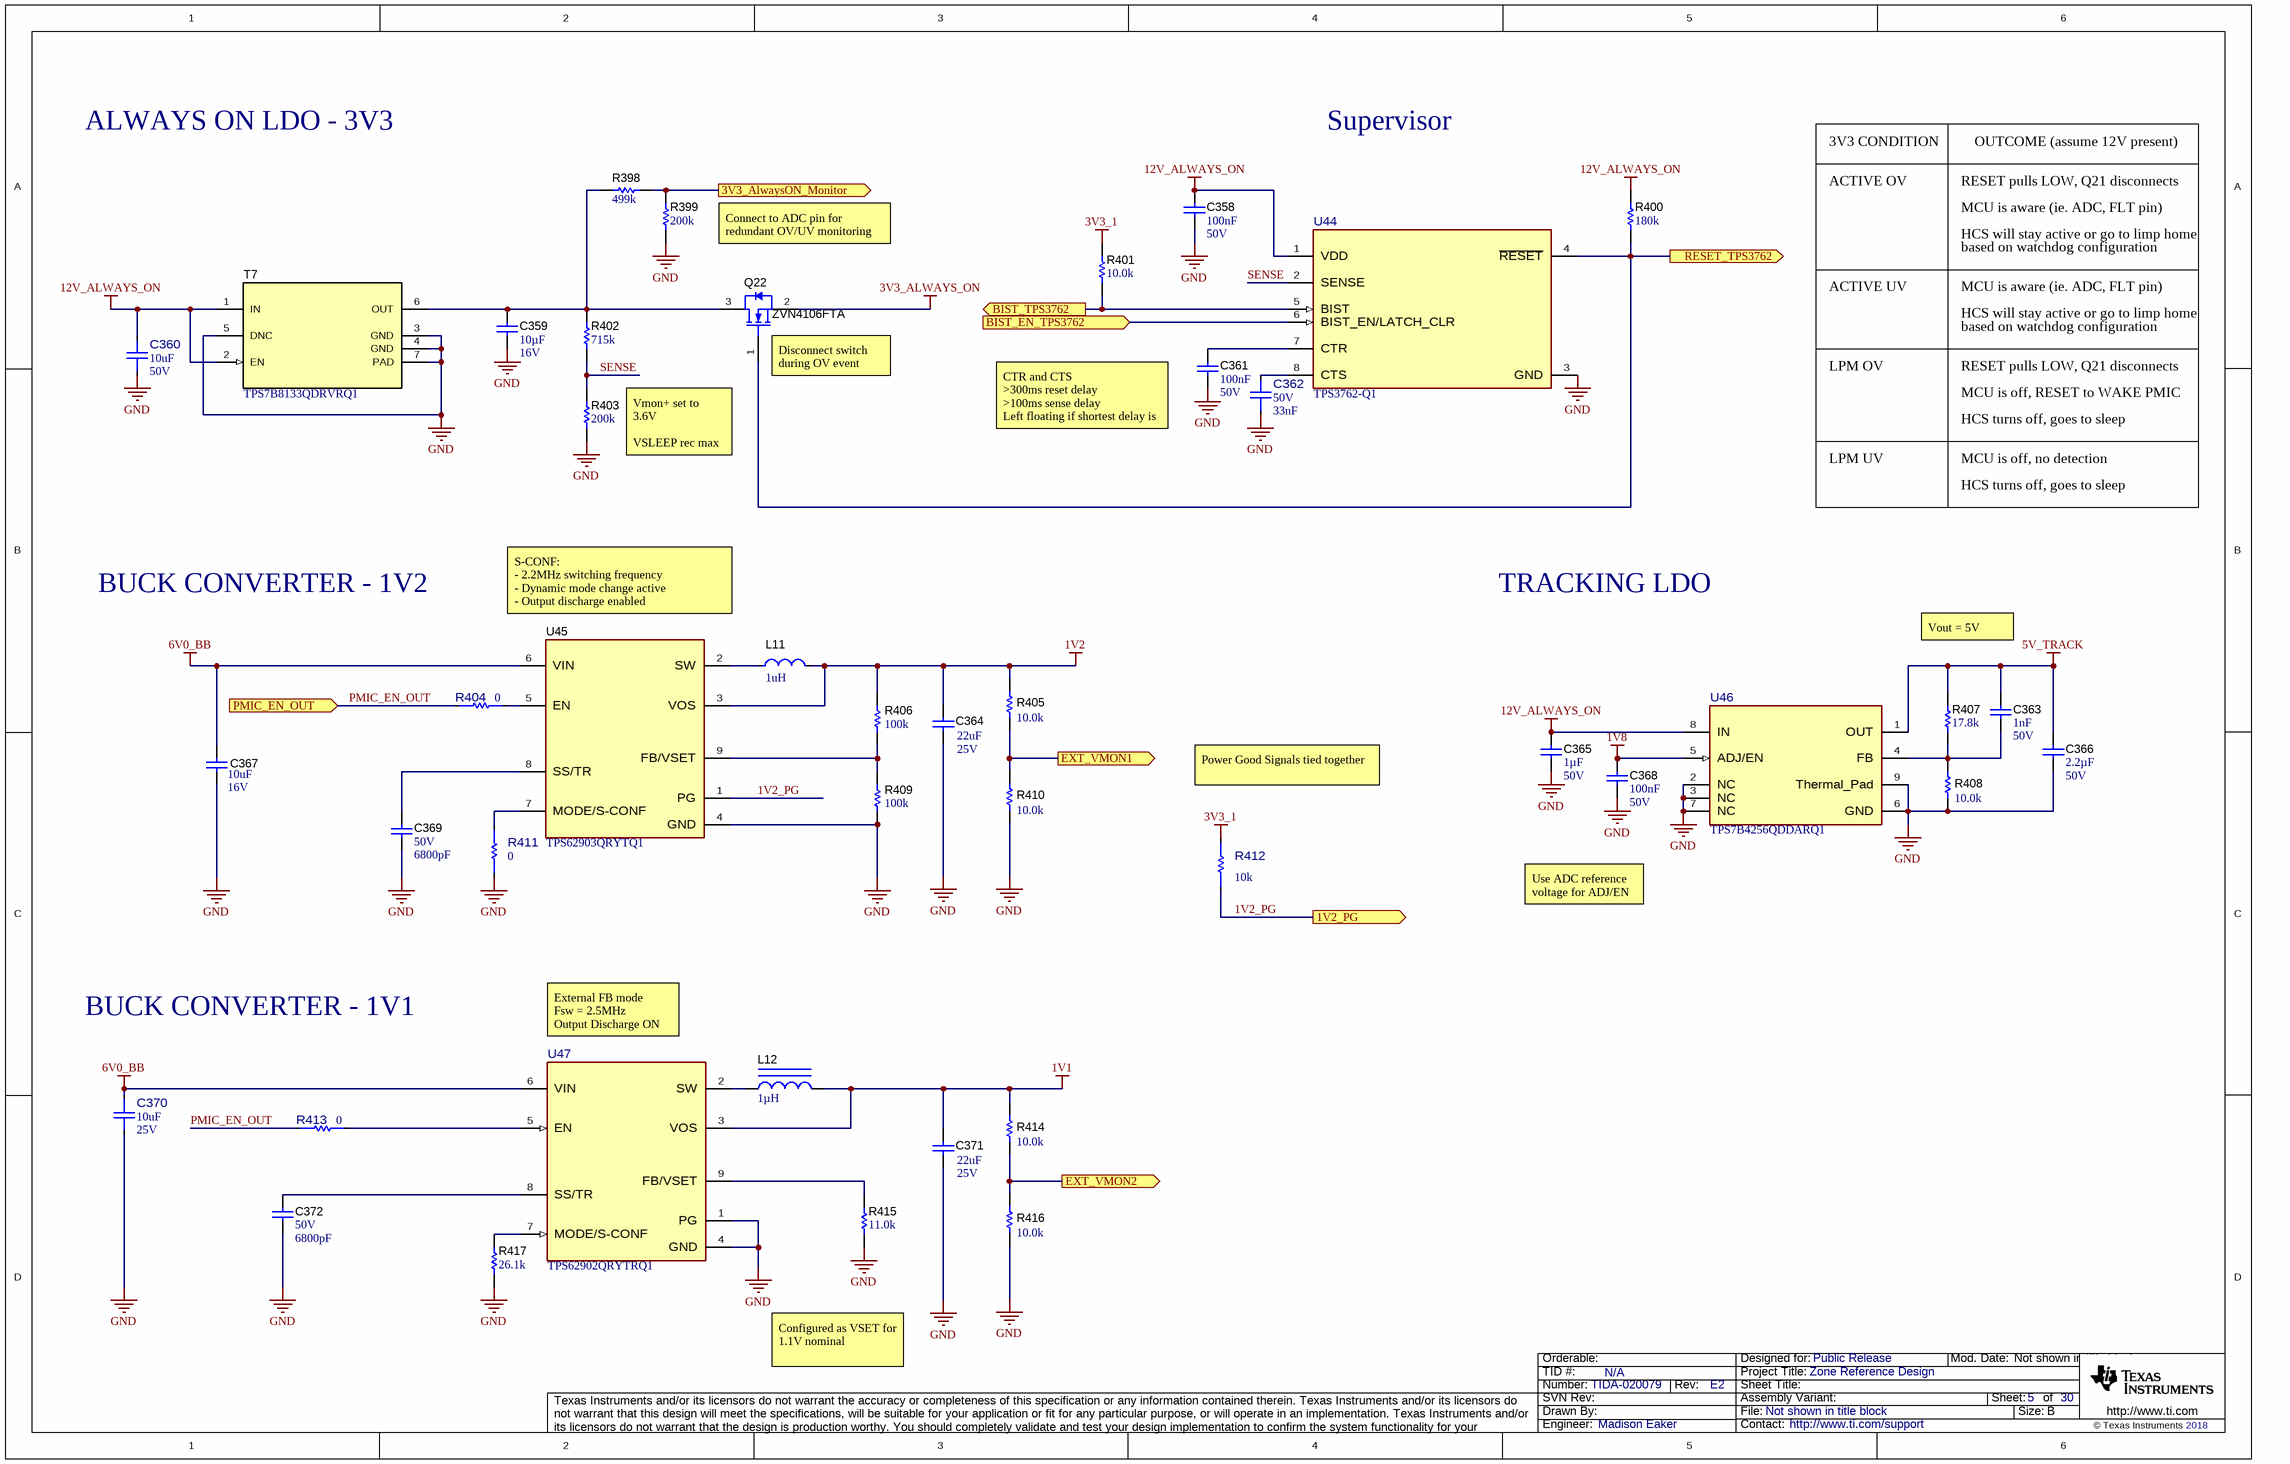
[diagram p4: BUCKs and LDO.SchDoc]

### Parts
C358  Cap_F: 100nF  VDC_V: 50V  [0603]  (hidden comment: 06035C104KAZ2A)
C359  Cap_F: 10µF  VDC_V: 16V  [0805_HV]  (hidden comment: CL21B106KOQNNNG)
C360  ValueDisplayed: 10uF  VDC_V: 50V  [FP-GMC31X7R106K50NT_1206-MFG]  (hidden comment: GMC31X7R106K50NT)
C361  Cap_F: 100nF  VDC_V: 50V  [0603]  (hidden comment: 06035C104KAZ2A)
C362  VDC_V: 50V  Cap_F: 33nF  [FP-CGA3E2X7R1H333K080AA_0603-MFG]  (hidden comment: CGA3E2X7R1H333K080AA)
C363  Cap_F: 1nF  VDC_V: 50V  [0603]  (hidden comment: C0603C102J5RACAUTO)
C364  VDC_V: 25V  ValueDisplayed: 22uF  [0805_HV]  (hidden comment: GRM21BR61E226ME44L)
C365  Cap_F: 1µF  VDC_V: 50V  [0805_HV]  (hidden comment: GCJ21BR71H105MA01L)
C366  Cap_F: 2.2µF  VDC_V: 50V  [0805_HV]  (hidden comment: CGA4J3X7R1H225K125AE)
C367  VDC_V: 16V  ValueDisplayed: 10uF  [0603]  (hidden comment: GRM188R61C106MAALD)
C368  Cap_F: 100nF  VDC_V: 50V  [0603]  (hidden comment: 06035C104KAZ2A)
C369  VDC_V: 50V  ValueDisplayed: 6800pF  [0402]  (hidden comment: GRM155R71H682KA88D)
C370  ValueDisplayed: 10uF  VDC_V: 25V  [FP-885012106031_0603-MFG]  (hidden comment: 885012106031)
C371  VDC_V: 25V  ValueDisplayed: 22uF  [0805_HV]  (hidden comment: GRM21BR61E226ME44L)
C372  VDC_V: 50V  ValueDisplayed: 6800pF  [0402]  (hidden comment: GRM155R71H682KA88D)
L11  value 1uH  [FP-XGL4030-102MEC_SMD_IND_4MM0_4MM0-MFG]  (hidden comment: XGL4030-102MEC)
L12  ValueDisplayed: 1µH  [TFM201610ALMA]  (hidden comment: TFM201610ALMA1R0MTAA)
Q22  ZVN4106FTA  [SOT-23]
R398  ValueDisplayed: 499k  [0603]  (hidden comment: RT0603BRD07499KL)
R399  ValueDisplayed: 200k  [0603]  (hidden comment: RT0603BRD07200KL)
R400  ValueDisplayed: 180k  [0603]  (hidden comment: RT0603BRD07180KL)
R401  ValueDisplayed: 10.0k  [TNPW0603]  (hidden comment: TNPW060310K0BEEA)
R402  ValueDisplayed: 715k  [0603]  (hidden comment: CRCW0603715KFKEA)
R403  ValueDisplayed: 200k  [0603]  (hidden comment: CRCW0603200KFKEA)
R404  value 0  [FP-ERJ-2GE0R00X_0402-MFG]  (hidden comment: ERJ-2GE0R00X)
R405  value 10.0k  [0402]  (hidden comment: AC0402FR-0710KL)
R406  value 100k  [0402]  (hidden comment: CRCW0402100KJNED)
R407  ValueDisplayed: 17.8k  [0603]  (hidden comment: CRCW060317K8FKEA)
R408  value 10.0k  [0402]  (hidden comment: AC0402FR-0710KL)
R409  value 100k  [0402]  (hidden comment: CRCW0402100KJNED)
R410  value 10.0k  [0402]  (hidden comment: AC0402FR-0710KL)
R411  value 0  [FP-ERJ-2GE0R00X_0402-MFG]  (hidden comment: ERJ-2GE0R00X)
R412  value 10k  [FP-RC0402JR-0710KL_0402-MFG]  (hidden comment: RC0402JR-0710KL)
R413  value 0  [FP-ERJ-2GE0R00X_0402-MFG]  (hidden comment: ERJ-2GE0R00X)
R414  value 10.0k  [0402]  (hidden comment: AC0402FR-0710KL)
R415  ValueDisplayed: 11.0k  [0603]  (hidden comment: RG1608P-113-B-T5)
R416  value 10.0k  [0402]  (hidden comment: AC0402FR-0710KL)
R417  ValueDisplayed: 26.1k  [0402]  (hidden comment: CRCW040226K1FKED)
T7  TPS7B8133QDRVRQ1  [DRV0006A]
U44  TPS3762-Q1  [DDF0008A-MFG]
U45  TPS62903QRYTQ1  [RYT0009A-MFG]
U46  TPS7B4256QDDARQ1  [DDA0008A-MFG]
U47  TPS62902QRYTRQ1  [RYT0009A-MFG]

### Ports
1V2_PG (out), 3V3_AlwaysON_Monitor (out), BIST_EN_TPS3762 (in), BIST_TPS3762 (out), EXT_VMON1 (out), EXT_VMON2 (out), PMIC_EN_OUT (in), RESET_TPS3762 (out)

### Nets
1V1: C371.1 L12.2 R414.2 U47.3(VOS)
1V2: C364.1 L11.2 R405.2 R406.2 U45.3(VOS)
1V8: C368.1 U46.5(ADJ/EN)
3V3_1: R401.2 R412.2
3V3_ALWAYS_ON: Q22.2(S)
5V_TRACK: C363.1 C366.1 R407.2 U46.1(OUT)
6V0_BB: C367.1 C370.1 U45.6(VIN) U47.6(VIN)
12V_ALWAYS_ON: C358.1 C360.2 C365.1 R400.2 T7.1(IN) T7.2(EN) U44.1(VDD) U46.8(IN)
GND: C358.2 C359.2 C360.1 C361.2 C362.1 C364.2 C365.2 C366.2 C367.2 C368.2 C369.2 C370.2 C371.2 C372.2 R399.1 R403.1 R408.1 R409.1 R410.1 R411.1 R415.2 R416.1 R417.2 T7.3(GND) T7.4(GND) T7.5(DNC) T7.7(PAD) U44.3(GND) U45.4(GND) U46.2(NC) U46.3(NC) U46.6(GND) U46.7(NC) U46.9(Thermal_Pad) U47.1(PG) U47.4(GND)
1V2_PG: R412.1 U45.1(PG) ; port 1V2_PG
3V3_ADC: R398.1 R399.2 ; port 3V3_AlwaysON_Monitor
BIST_EN_TPS3762: U44.6(BIST_EN/LATCH_CLR) ; port BIST_EN_TPS3762
BIST_TPS3762: R401.1 U44.5(BIST) ; port BIST_TPS3762
EXT_VMON1: R405.1 R410.2 ; port EXT_VMON1
EXT_VMON2: R414.1 R416.2 ; port EXT_VMON2
PMIC_EN_OUT: R404.1 R413.1 ; port PMIC_EN_OUT
RESET_TPS: Q22.1(G) R400.1 U44.4(~{RESET}) ; port RESET_TPS3762
SENSE: R402.1 R403.2 U44.2(SENSE)  [project net SENSE_5]
NetC359_1: C359.1 Q22.3(D) R398.2 R402.2 T7.6(OUT)
NetC361_1: C361.1 U44.7(CTR)
NetC362_2: C362.2 U44.8(CTS)
NetC363_2: C363.2 R407.1 R408.2 U46.4(FB)
NetC369_1: C369.1 U45.8(SS/TR)
NetC372_1: C372.1 U47.8(SS/TR)
NetL11_1: L11.1 U45.2(SW)
NetL12_1: L12.1 U47.2(SW)
NetR404_2: R404.2 U45.5(EN)
NetR406_1: R406.1 R409.2 U45.9(FB/VSET)
NetR411_2: R411.2 U45.7(MODE/S-CONF)
NetR413_2: R413.2 U47.5(EN)
NetR415_1: R415.1 U47.9(FB/VSET)
NetR417_1: R417.1 U47.7(MODE/S-CONF)

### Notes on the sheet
- ALWAYS ON LDO - 3V3
- Supervisor
- 3V3 CONDITION
- OUTCOME (assume 12V present)
- ACTIVE OV
- RESET pulls LOW, Q21 disconnects
- MCU is aware (ie. ADC, FLT pin)
- Connect to ADC pin for redundant OV/UV monitoring
- ACTIVE UV
- HCS will stay active or go to limp home
- based on watchdog configuration
- (near Q22) Disconnect switch during OV event
- (near C361) CTR and CTS
  >300ms reset delay
  >100ms sense delay
  Left floating if shortest delay is needed.
- LPM OV
- MCU is off, RESET to WAKE PMIC
- HCS turns off, goes to sleep
- Vmon+ set to 3.6V
  VSLEEP rec max 3.63V
- LPM UV
- MCU is off, no detection
- BUCK CONVERTER - 1V2
- S-CONF:
  - 2.2MHz switching frequency
  - Dynamic mode change active
  - Output discharge enabled
- TRACKING LDO
- Vout = 5V
- Power Good Signals tied together
- Use ADC reference voltage for ADJ/EN
- BUCK CONVERTER - 1V1
- External FB mode             Fsw = 2.5MHz                                                              Output Discharge ON
- Configured as VSET for 1.1V nominal

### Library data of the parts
C358 C361 C368 = CMP-0079095-1: CAP, CERM, 0.1 µF, 50 V,+/- 10%, X7R, AEC-Q200 Grade 1, 0603; Manufacturer: AVX; SizeAreaWB_mm2: 4.68; SizeArea_mm2: 1.28; AEC Qualified: Y; AEC Category: Q200; Value: 0.1uF; TaMax_C: 125°C; SizeZ_mm: 1; Polarized: N; TaMin_C: -55°C; SizeY_mm: 0.8; U/M: EA; SizeX_mm: 1.6; ValueDisplayed: 0.1µF
C359 = CMP-0860967-1: CAP, CERM, 10 µF, 16 V,+/- 10%, X7R, 0805; Manufacturer: Samsung; U/M: EA; AEC Qualified: N; SizeZ_mm: 1.45; TaMax_C: 125°C; TaMin_C: -55°C; Value: 10uF; SizeAreaWB_mm2: 6.75; SizeArea_mm2: 2.5; Cap_Case: 0805; SizeY_mm: 1.25; AEC Category: Q200; SizeX_mm: 2
C360 = CMP-0093201-1: 10 µF ±10% 50V Ceramic Capacitor X7R 1206 (3216 Metric); Manufacturer: Cal-Chip Electronics; AEC Qualified: No; SizeZ_mm: 1.8mm; TempCo: 15%; Value: 10µF
C362 = CMP-0090210-1: Cap Ceramic 33nF 50V X7R 10% Pad SMD 0603 +125°C Automotive T/R; Manufacturer: TDK; AEC Qualified: Yes; AEC Grade: Grade 1; Tolerance_%: 0.1%; TempCo: 0.15; SizeZ_mm: 1.1mm
C363 = CMP-0006844-3: CAP, CERM, 1000 pF, 50 V, +/- 5%, X7R, AEC-Q200 Grade 1, 0603; Manufacturer: Kemet; TaMin_C: -55°C; Polarized: N; SizeAreaWB_mm2: 4.68; Value1: Unknown; U/M: EA; Value: 1000pF; TaMax_C: 125°C; SizeZ_mm: 1; SizeX_mm: 1.6; SizeY_mm: 0.8; SizeArea_mm2: 1.28; AEC Qualified: Y; AEC Category: Q200
C364 C371 = CMP-0008305-2: as C282 on sheet PMIC
C365 = CMP-0080480-1: CAP, CERM, 1 µF, 50 V,+/- 20%, X7R, AEC-Q200 Grade 1, 0805; Manufacturer: MuRata; TaMin_C: -55°C; Polarized: N; SizeAreaWB_mm2: 6.75; U/M: EA; Value: 1uF; TaMax_C: 125°C; SizeZ_mm: 1.45; SizeX_mm: 2; SizeY_mm: 1.25; Cap_Case: 0805; SizeArea_mm2: 2.5; AEC Qualified: Y; AEC Grade: 1; AEC Category: Q200
C366 = CMP-0860897-1: CAP, CERM, 2.2 µF, 50 V,+/- 10%, X7R, AEC-Q200 Grade 1, 0805; Manufacturer: TDK; SizeAreaWB_mm2: 6.75; U/M: EA; TaMin_C: -55°C; Cap_Case: 0805; Value: 2.2uF; AEC Category: Q200; SizeArea_mm2: 2.5; SizeY_mm: 1.25; Polarized: N; AEC Grade: 1; SizeZ_mm: 1.45; AEC Qualified: Y; TaMax_C: 125°C; SizeX_mm: 2
C367 = CMP-0007336-5: CAP, CERM, 10 uF, 16 V, +/- 20%, X5R, 0603; Manufacturer: MuRata; TaMin_C: -55°C; Polarized: N; SizeAreaWB_mm2: 4.68; Value1: Unknown; U/M: EA; Value: 10uF; TaMax_C: 85°C; SizeZ_mm: 1; SizeX_mm: 1.6; SizeY_mm: 0.8; SizeArea_mm2: 1.28; Cap_F: 10µF; AEC Category: Q200
C369 C372 = CMP-0006696-2: CAP, CERM, 6800 pF, 50 V, +/- 10%, X7R, 0402; Manufacturer: MuRata; TaMin_C: -55°C; Polarized: N; SizeAreaWB_mm2: 3; Value1: Unknown; U/M: EA; Value: 6800pF; TaMax_C: 125°C; SizeZ_mm: 0.6; SizeX_mm: 1; SizeY_mm: 0.5; Cap_F: 6.8nF; AEC Category: Q200
C370 = CMP-0096736-1: 10 µF ±20% 25V Ceramic Capacitor X5R 0603 (1608 Metric); Manufacturer: Wurth; Cap_F: 10µF; AEC Qualified: No; SizeZ_mm: 1mm; Value: 10µF; TempCo: 15%
L11 = CMP-0090842-1: Power Inductor, shielded, composite, 1uH 20% tol, DCR 7.2mOhms, SRF 65MHz, Isat 4.8A, Irms 13A, AEC-Q200; Manufacturer: Coilcraft; TaMin_C: -40°C; TaMax_C: +125°C; Test Frequency: 1MHz; DCR_ohm: 7.2m; AEC Grade: Grade 1; SizeZ_mm: 3.1mm; AEC Qualified: Yes; Shrouded: true; Ind_H: 1µH
L12 = CMP-0081092-1: Inductor, Shielded, Metal Composite, 1 µH, 3.1 A, 0.06 ohm, AEC-Q200 Grade 0, SMD; Manufacturer: TDK; Isat: 3.3A @ 30% inductance drop; Irms: 3.1A @ 40C rise; SizeAreaWB_mm2: 7.8; DCR_ohm: 60m; Value: 1uH; Imax_A: 3.1A; SizeZ_mm: 1; SizeX_mm: 2; SizeY_mm: 1.6; SizeArea_mm2: 3.2; AEC Qualified: Y; AEC Grade: 0; AEC Category: Q200
Q22 = CMP-0000887-1: MOSFET, N-CH, 60 V, 0.2 A, AEC-Q101, SOT-23; Alternate Manufacturer: None; Manufacturer: Diodes Inc.; SizeZ_mm: 1.1; ChType: N; VdsMax_V: 60V; SizeX_mm: 2.5; SizeY_mm: 3; Vgs_V: 20V; AEC Qualified: Y; Value: 60V; SizeArea_mm2: 7.5; AEC Category: Q101; IdsMax_A: 200mA; SizeAreaWB_mm2: 14; U/M: EA
R398 = CMP-0024280-3: RES, 499 k, 0.1%, 0.1 W, 0603; Manufacturer: Yageo America; Power_W: 100mW; TempCo: 25 ppm/C; U/M: EA; Value: 499k; EIA_Code: E192; SizeX_mm: 1.6; SizeY_mm: 0.8; SizeZ_mm: 1; Value2: 0.1W; SizeArea_mm2: 1.28; VDC_V: 75V; AEC Category: Q200
R399 = CMP-0023920-1: RES, 200 k, 0.1%, 0.1 W, 0603; Manufacturer: Yageo America; Power_W: 100mW; TempCo: 25 ppm/C; U/M: EA; Value: 200k; EIA_Code: E192; SizeX_mm: 1.6; SizeY_mm: 0.8; SizeZ_mm: 1; Value2: 0.1W; SizeArea_mm2: 1.28; VDC_V: 75V; AEC Category: Q200
R400 = CMP-0023826-3: RES, 180 k, 0.1%, 0.1 W, 0603; Manufacturer: Yageo America; Power_W: 100mW; TempCo: 25 ppm/C; U/M: EA; Value: 180k; EIA_Code: E192; SizeX_mm: 1.6; SizeY_mm: 0.8; SizeZ_mm: 1; Value2: 0.1W; SizeArea_mm2: 1.28; VDC_V: 75V; AEC Category: Q200
R401 = CMP-0025686-1: RES, 10.0 k, 0.1%, 0.1 W, AEC-Q200 Grade 1, 0603; Manufacturer: Vishay-Dale; Power_W: 100mW; TempCo: 25 ppm/C; Value_Code: 10k0; U/M: EA; Value: 10.0k; EIA_Code: E192; Res_ohm: 10k; SizeX_mm: 1.6; SizeY_mm: 0.85; SizeZ_mm: 0.55; Value2: 0.1W; SizeArea_mm2: 1.36; AEC Qualified: Y; VDC_V: 75V; AEC Grade: 1; AEC Category: Q200
R402 = CMP-0022579-4: RES, 715 k, 1%, 0.1 W, AEC-Q200 Grade 0, 0603; Manufacturer: Vishay-Dale; Power_W: 100mW; TempCo: 100 ppm/C; Value: 715k; EIA_Code: E96; SizeX_mm: 1.6; SizeY_mm: 0.8; SizeZ_mm: 1; Value2: 0.1W; SizeArea_mm2: 1.28; AEC Qualified: Y; VDC_V: 75V; AEC Category: Q200; AEC Grade: 0
R403 = CMP-0022200-4: RES, 200 k, 1%, 0.1 W, AEC-Q200 Grade 0, 0603; Manufacturer: Vishay-Dale; Power_W: 100mW; TempCo: 100 ppm/C; Value: 200k; EIA_Code: E96; SizeX_mm: 1.6; SizeY_mm: 0.8; SizeZ_mm: 1; Value2: 0.1W; SizeArea_mm2: 1.28; AEC Qualified: Y; VDC_V: 75V; AEC Category: Q200; AEC Grade: 0
R404 R411 R413 = CMP-0002710-1: as R335 on sheet PMIC
R405 R408 R410 R414 R416 = CMP-0077731-1: RES, 10.0 k, 1%, 0.063 W, AEC-Q200 Grade 0, 0402; Manufacturer: Yageo America; Power_W: 63mW; TempCo: 100 ppm/C; Value_Code: 10k0; U/M: EA; EIA_Code: E96; Res_ohm: 10k; SizeX_mm: 1.0; SizeY_mm: 0.5; SizeZ_mm: 0.6; Value2: 0.063W; AEC Qualified: Y; VDC_V: 50V; AEC Grade: 0; AEC Category: Q200
R406 R409 = CMP-0026823-3: RES, 100 k, 5%, 0.063 W, AEC-Q200 Grade 0, 0402; Manufacturer: Vishay-Dale; Power_W: 63mW; TempCo: 200 ppm/C; EIA_Code: E24; SizeX_mm: 1; SizeY_mm: 0.5; SizeZ_mm: 0.6; Value2: 0.063W; AEC Qualified: Y; VDC_V: 50V; AEC Category: Q200; AEC Grade: 0
R407 = CMP-0022090-4: RES, 17.8 k, 1%, 0.1 W, AEC-Q200 Grade 0, 0603; Manufacturer: Vishay-Dale; Power_W: 100mW; TempCo: 100 ppm/C; Value_Code: 17k8; Value: 17.8k; EIA_Code: E96; SizeX_mm: 1.6; SizeY_mm: 0.8; SizeZ_mm: 1; Value2: 0.1W; SizeArea_mm2: 1.28; AEC Qualified: Y; VDC_V: 75V; AEC Category: Q200; AEC Grade: 0
R412 = CMP-0094798-1: Res Thick Film 0402 10K Ohm 5% 0.063W(1/16W) ±100ppm/C Pad SMD T/R; Manufacturer: YAGEO; Power_W: 63mW; TempCo: 100ppm/°C; SizeZ_mm: 0.4mm; AEC Qualified: No; VDC_V: 50V; Category Cd01000Bfc2916C6: Single Components; Category 5C6A91606D4187Ad: Resistors; Category 7542B8484461Ae85: Passive Components
R415 = CMP-0023415-3: RES, 11.0 k, 0.1%, 0.1 W, 0603; Manufacturer: Susumu Co Ltd; Power_W: 100mW; TempCo: 25 ppm/C; Value_Code: 11k0; U/M: EA; Value: 11.0k; EIA_Code: E192; Res_ohm: 11k; SizeX_mm: 1.6; SizeY_mm: 0.8; SizeZ_mm: 1; Value2: 0.1W; SizeArea_mm2: 1.28; VDC_V: 75V; AEC Category: Q200
R417 = CMP-0026207-1: RES, 26.1 k, 1%, 0.063 W, 0402; Manufacturer: Vishay-Dale; Power_W: 63mW; TempCo: 100 ppm/C; Value_Code: 26k1; U/M: EA; Value: 26.1k; EIA_Code: E96; SizeX_mm: 1; SizeY_mm: 0.5; SizeZ_mm: 0.6; Value2: 0.063W; VDC_V: 50V; AEC Category: Q200
T7 = CMP-0860463-2: Automotive 150-mA high-voltage ultra-low-IQ low-dropout (LDO) linear regulator, DRV0006A (WSON-6); Alternate Manufacturer: Texas Instruments; AEC Qualified: Y; SizeY_mm: 2; SizeZ_mm: 0.8; AEC Category: Q200; CompType: IC; SizeArea_mm2: 4; SizeAreaWB_mm2: 9
U44 = CMP-0098319-1: Wide VIN 65 V Dual Channel Overvoltage & Undervoltage (OV & UV) Detector with Built-in Self-test for Automotive; Manufacturer: Texas Instruments; SizeZ_mm: 1.1mm; AEC Qualified: Yes; AEC Grade: Grade 1; Max Supply Voltage: 65V; Min Supply Voltage: 2.7V; Nominal Supply Current: 8.1-31.1uA; Number Of Outputs: 1; Reset Type: Active Low; Standoff Height: 0mm; TaMax_C: +150°C; TaMin_C: -40°C; TJmax_C: +125°C
U45 = CMP-0093448-1: 3-V to 18-V, High Efficiency and Low IQ Buck Converter in QFN HR  Package with 165C Junction temperature; Manufacturer: Texas Instruments; SizeZ_mm: 1.05mm; Min Supply Voltage: 3V; Output Type: AdjustableProgrammable; Switching Frequency: 1/2.5MHz; Max Supply Voltage: 18V; Output Voltage: 0.4-5.5V; Number Of Outputs: 1; TJmax_C: +165°C; Standoff Height: 0mm; Nominal Supply Current: 8mA; AEC Qualified: Yes; AEC Grade: Grade 1; Max Duty Cycle: 100%
U46 = CMP-0037155-1: 70-mA, 40-V, Voltage-Tracking LDO With 3-mV Tracking Tolerance; Manufacturer: Texas Instruments; SizeZ_mm: 1.7mm; AEC Qualified: Yes; AEC Grade: Grade 1; Dropout Voltage: 300mV; Max Supply Voltage: 40V; Min Supply Voltage: 3V; Nominal Supply Current: 34-45uA; Number Of Outputs: 1; Output Type: AdjustableProgrammable; Output Voltage: 2-40V; Standoff Height: 0mm; TaMax_C: +125°C; TaMin_C: -40°C; TJmax_C: +150°C
U47 = CMP-0121948-1: 3-V to 18-V, 2-A, Automotive Low IQ Buck Converter with +165°C TJ; Manufacturer: Texas Instruments; SizeZ_mm: 1.05mm; AEC Qualified: Yes; AEC Grade: Grade 1; Max Duty Cycle: 100%; Max Supply Voltage: 18V; Min Supply Voltage: 3V; Nominal Supply Current: 8mA; Number Of Outputs: 1; Output Type: AdjustableProgrammable; Output Voltage: 0.4-5.5V; Standoff Height: 0mm; Switching Frequency: 1/2.5MHz; TaMax_C: +125°C; TaMin_C: -40°C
